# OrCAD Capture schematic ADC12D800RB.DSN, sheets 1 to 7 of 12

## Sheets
1 Title Page
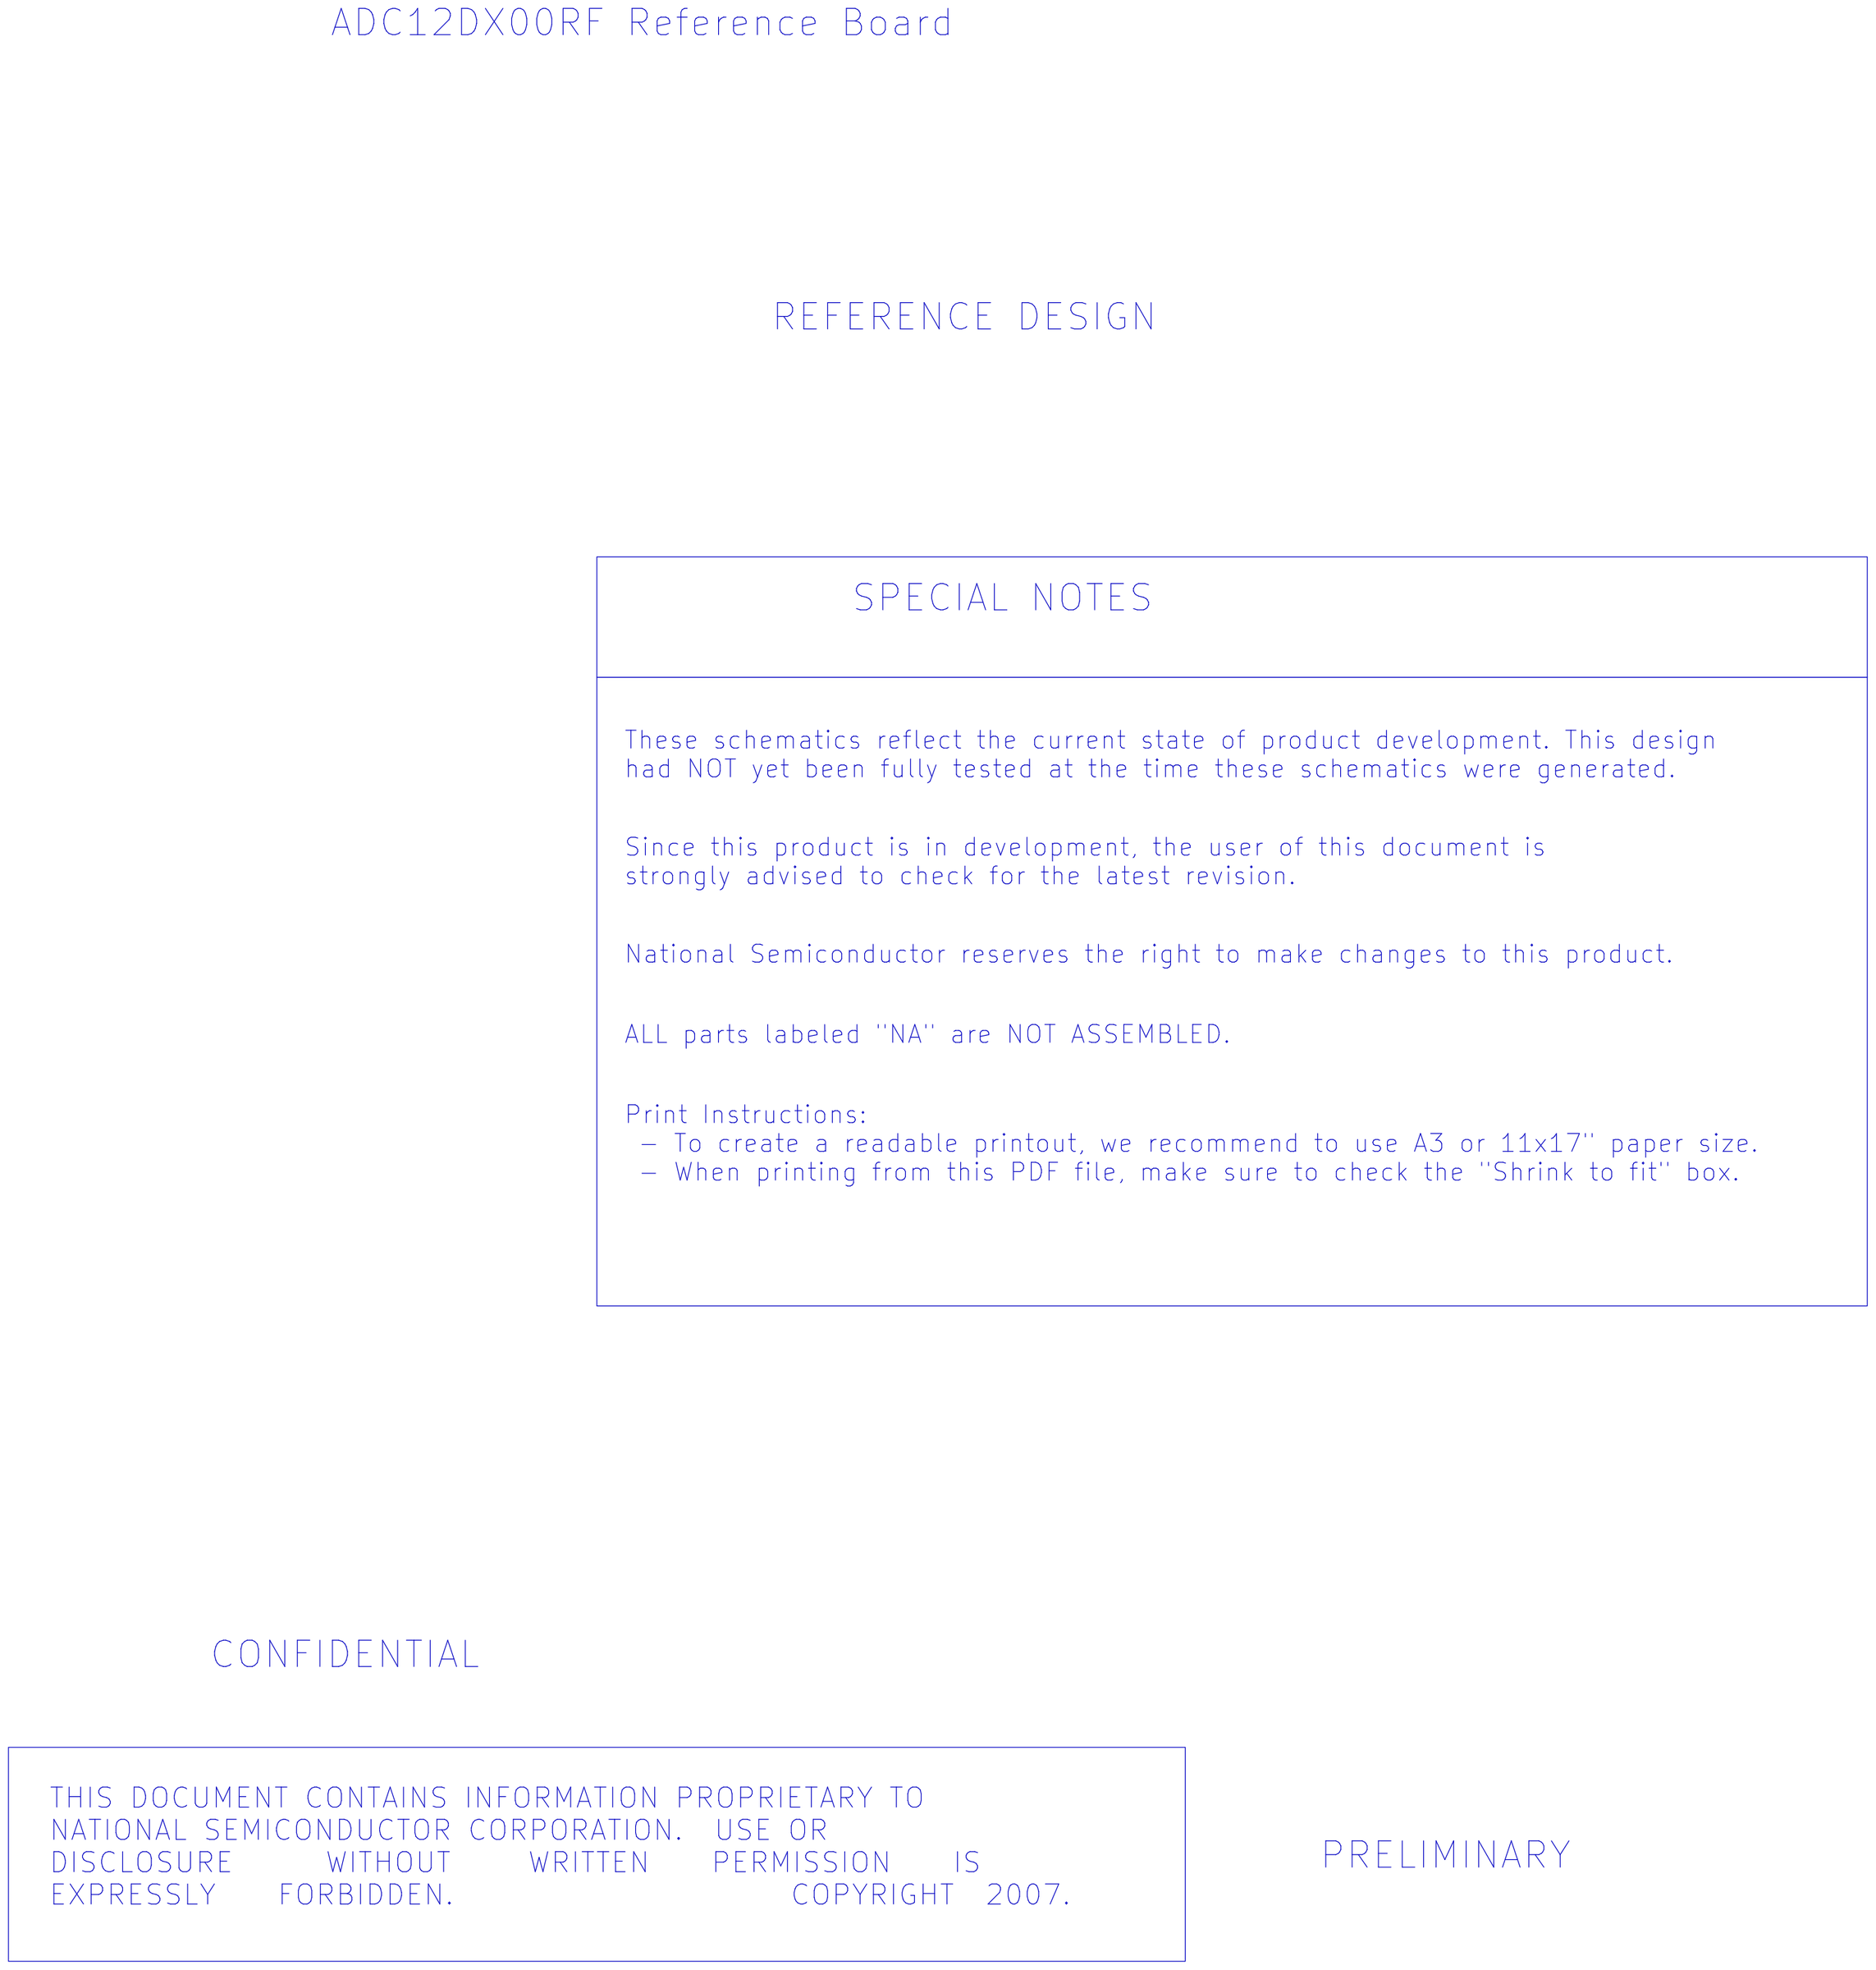
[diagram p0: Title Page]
2 TopBlock: size C
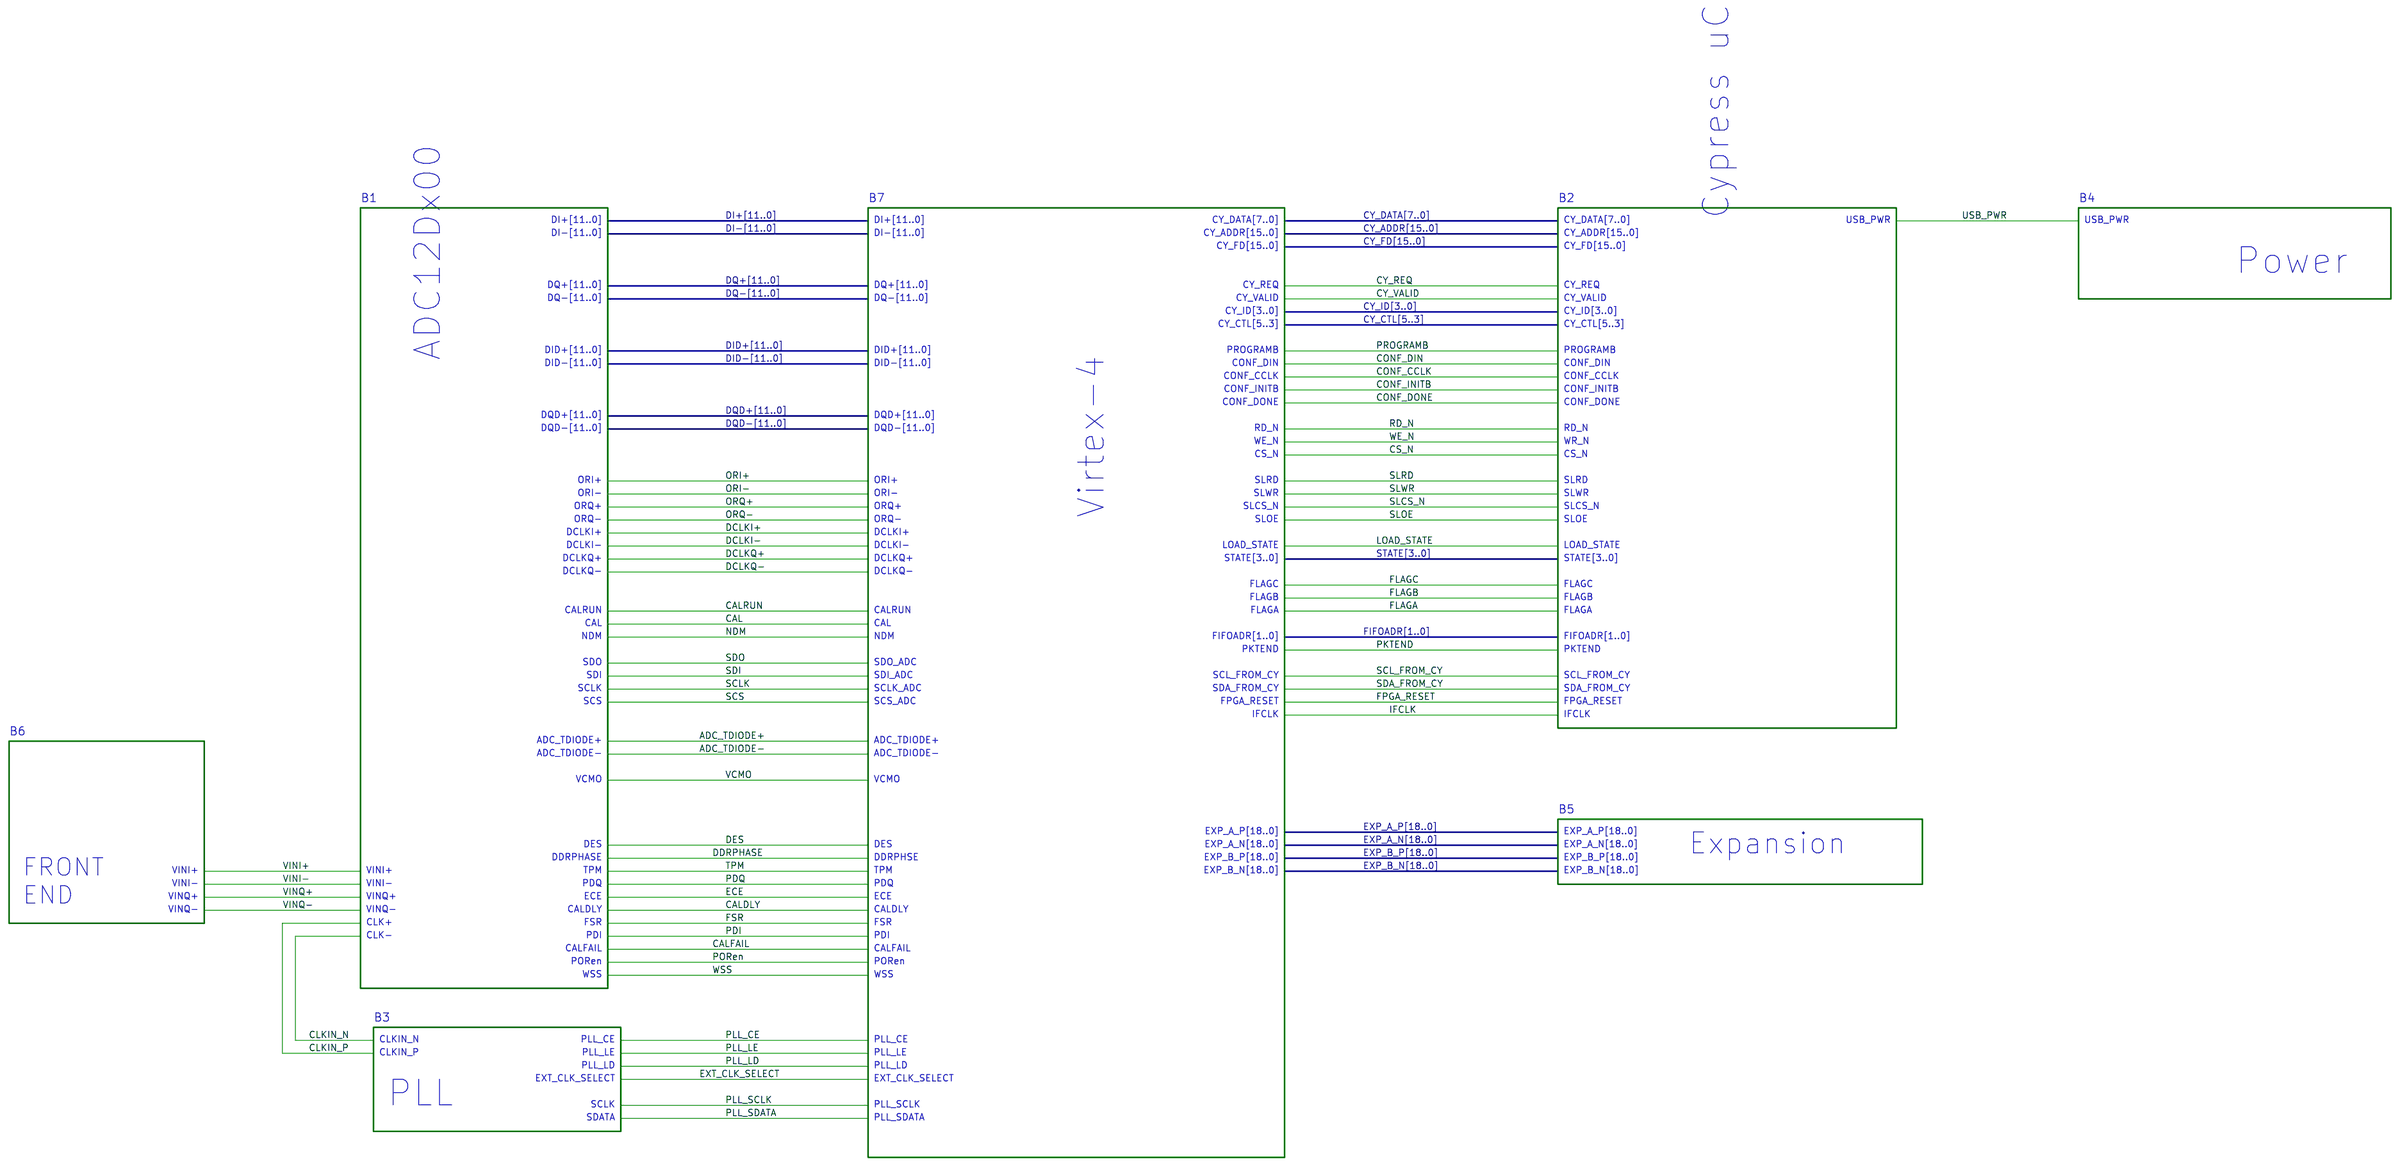
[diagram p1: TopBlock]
3 AD12DX00: size C; block B1
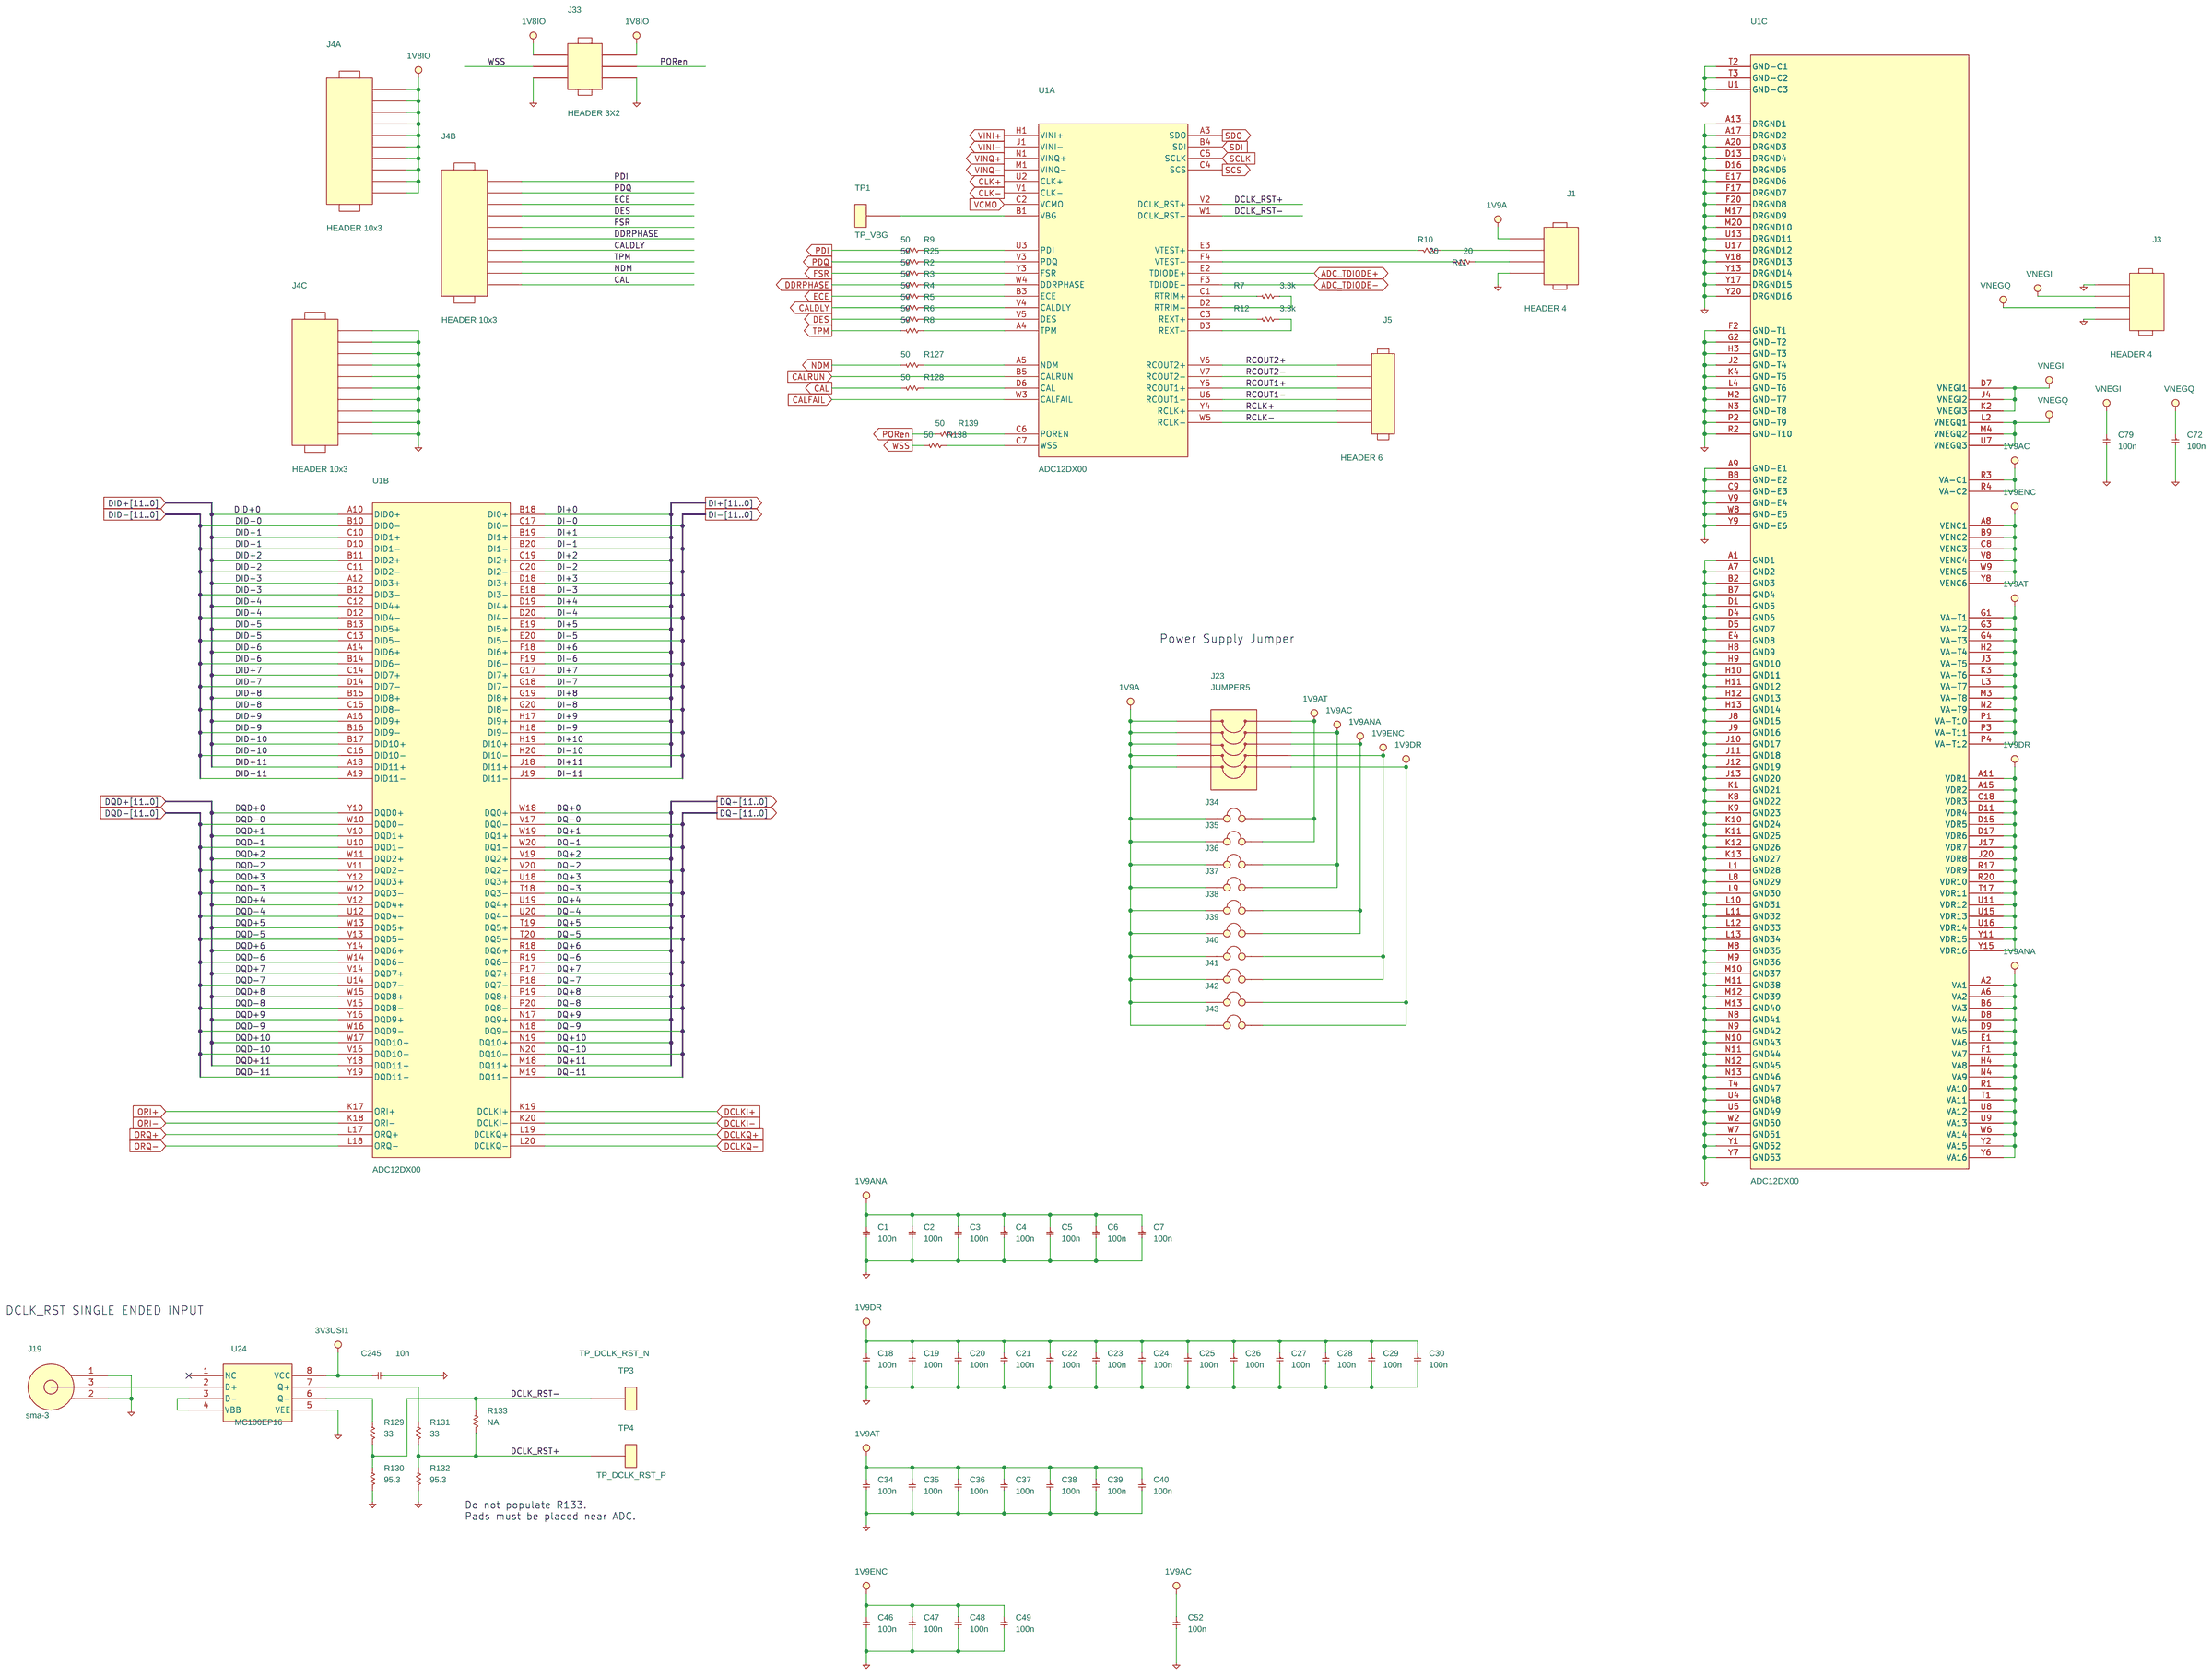
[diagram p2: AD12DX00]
4 Cypress: size C; block B2
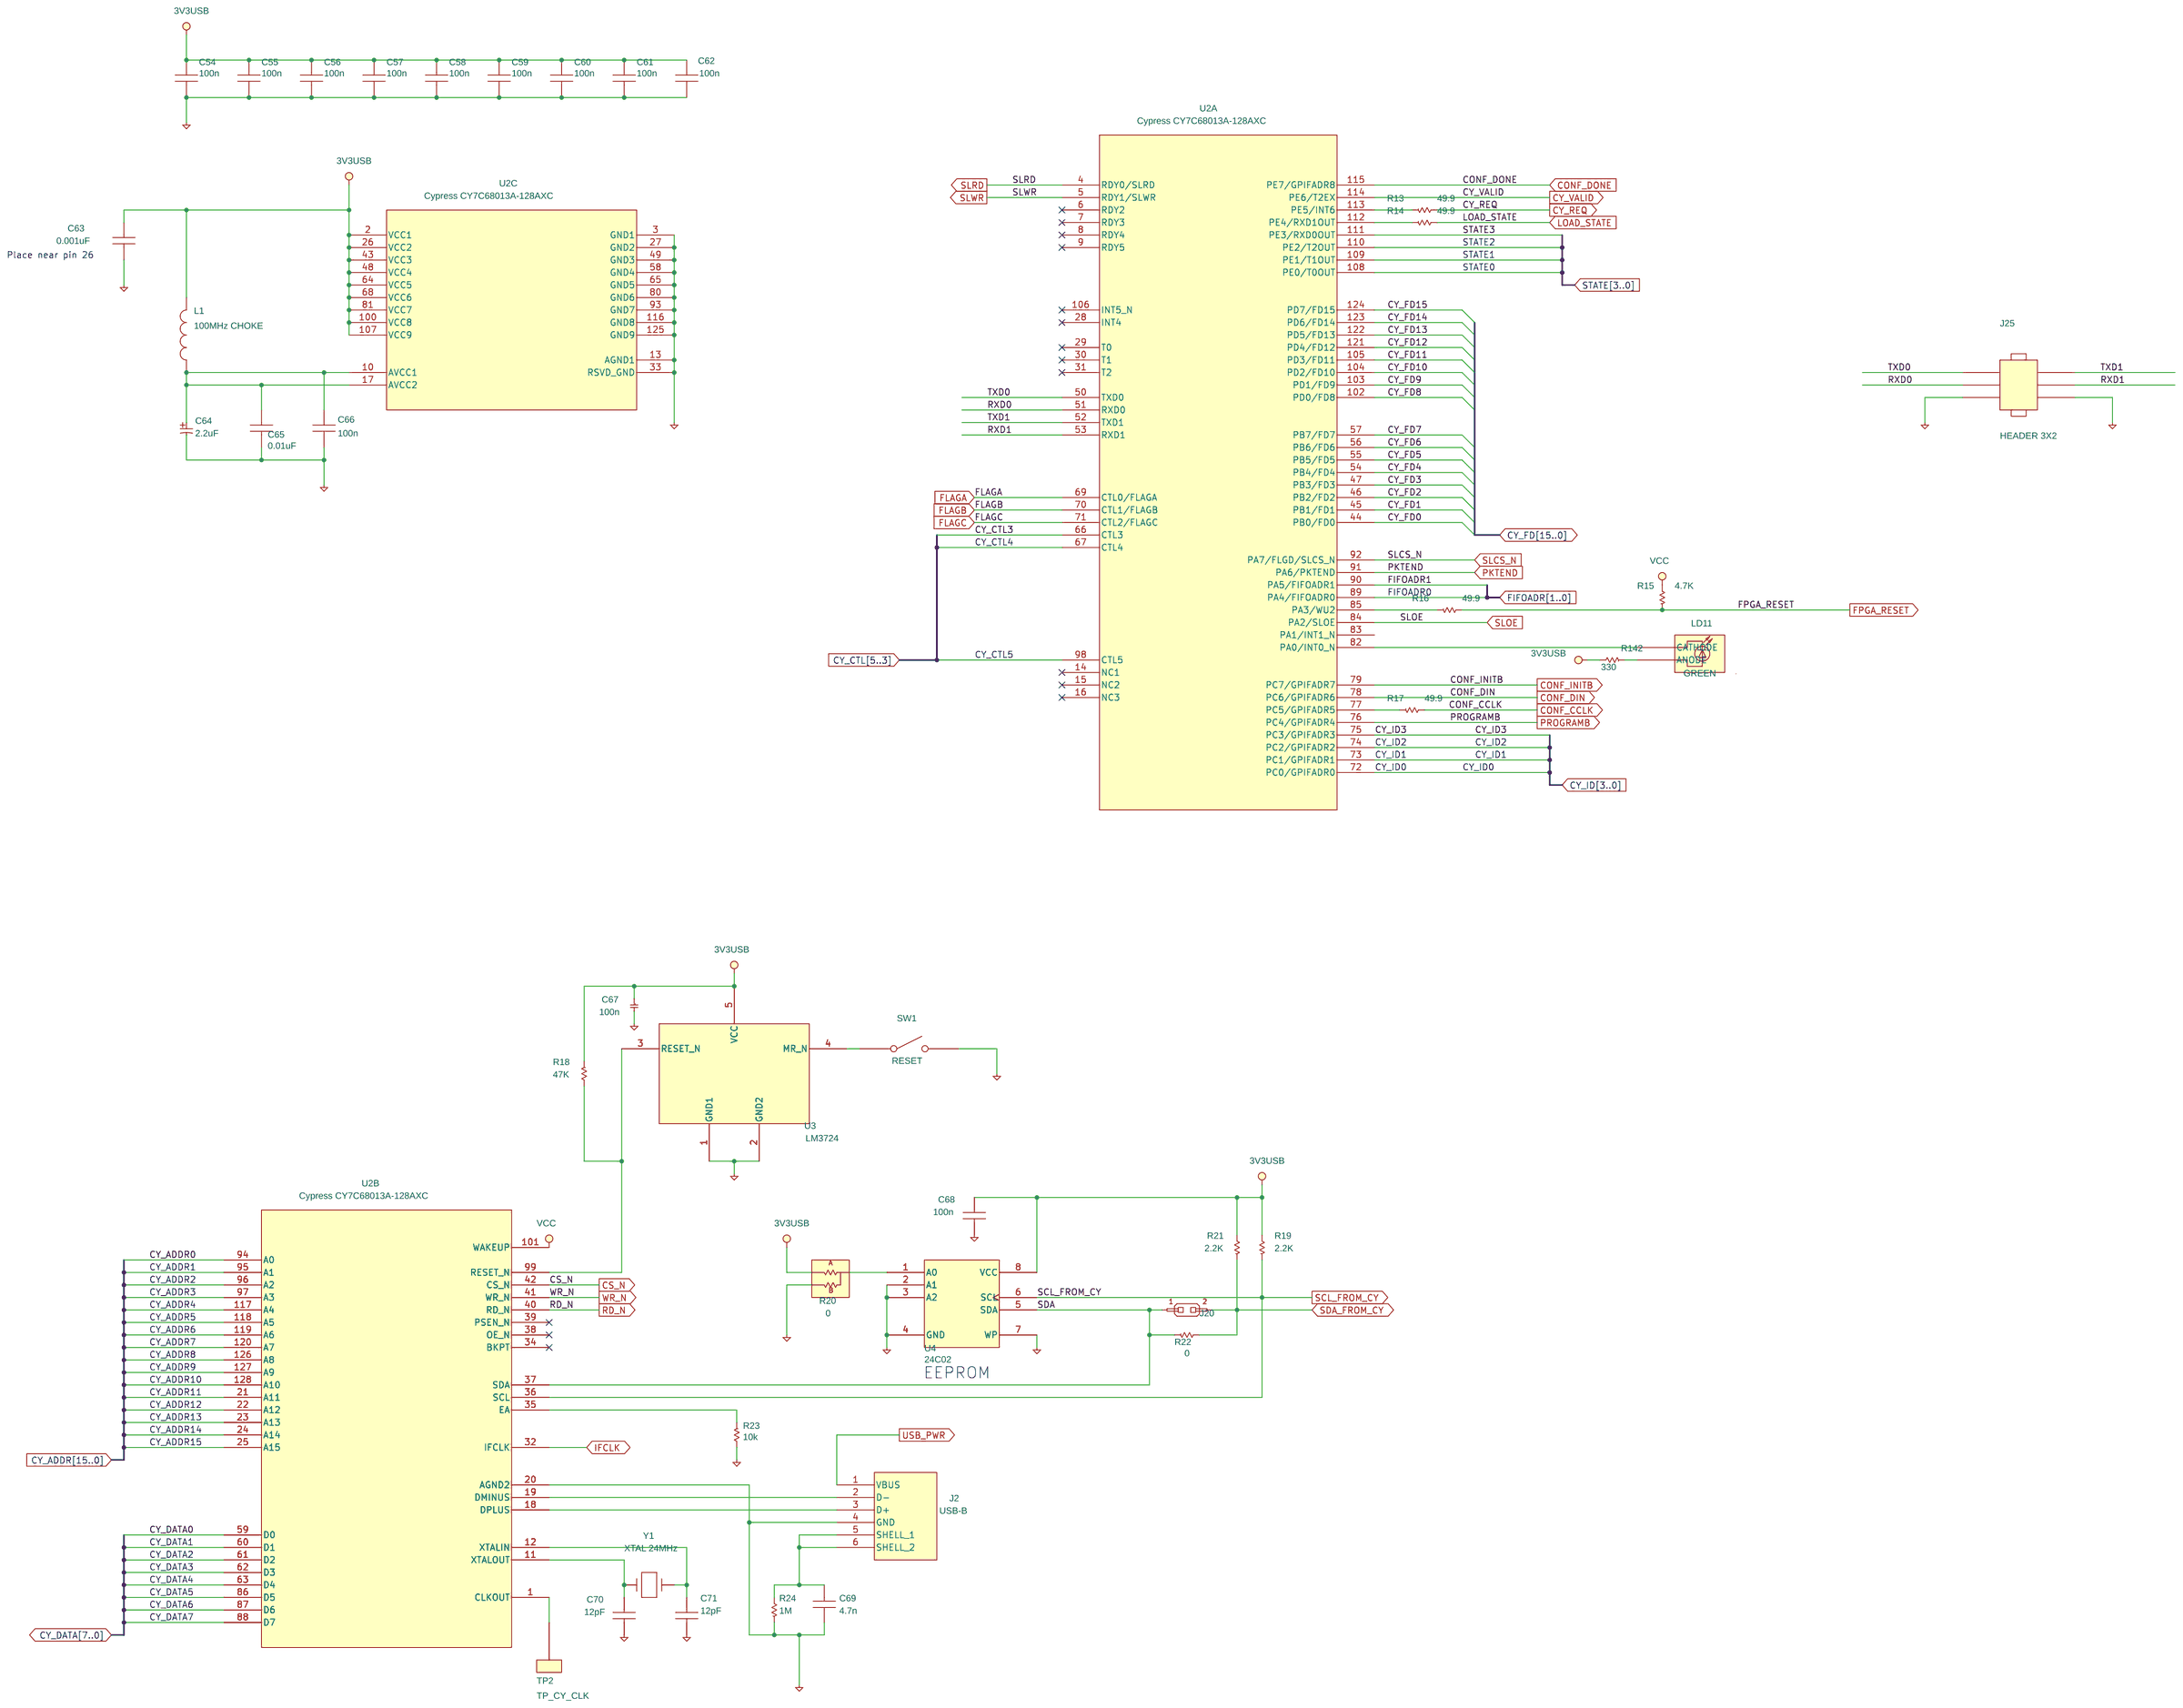
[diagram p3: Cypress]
5 Power1: size C; block B4
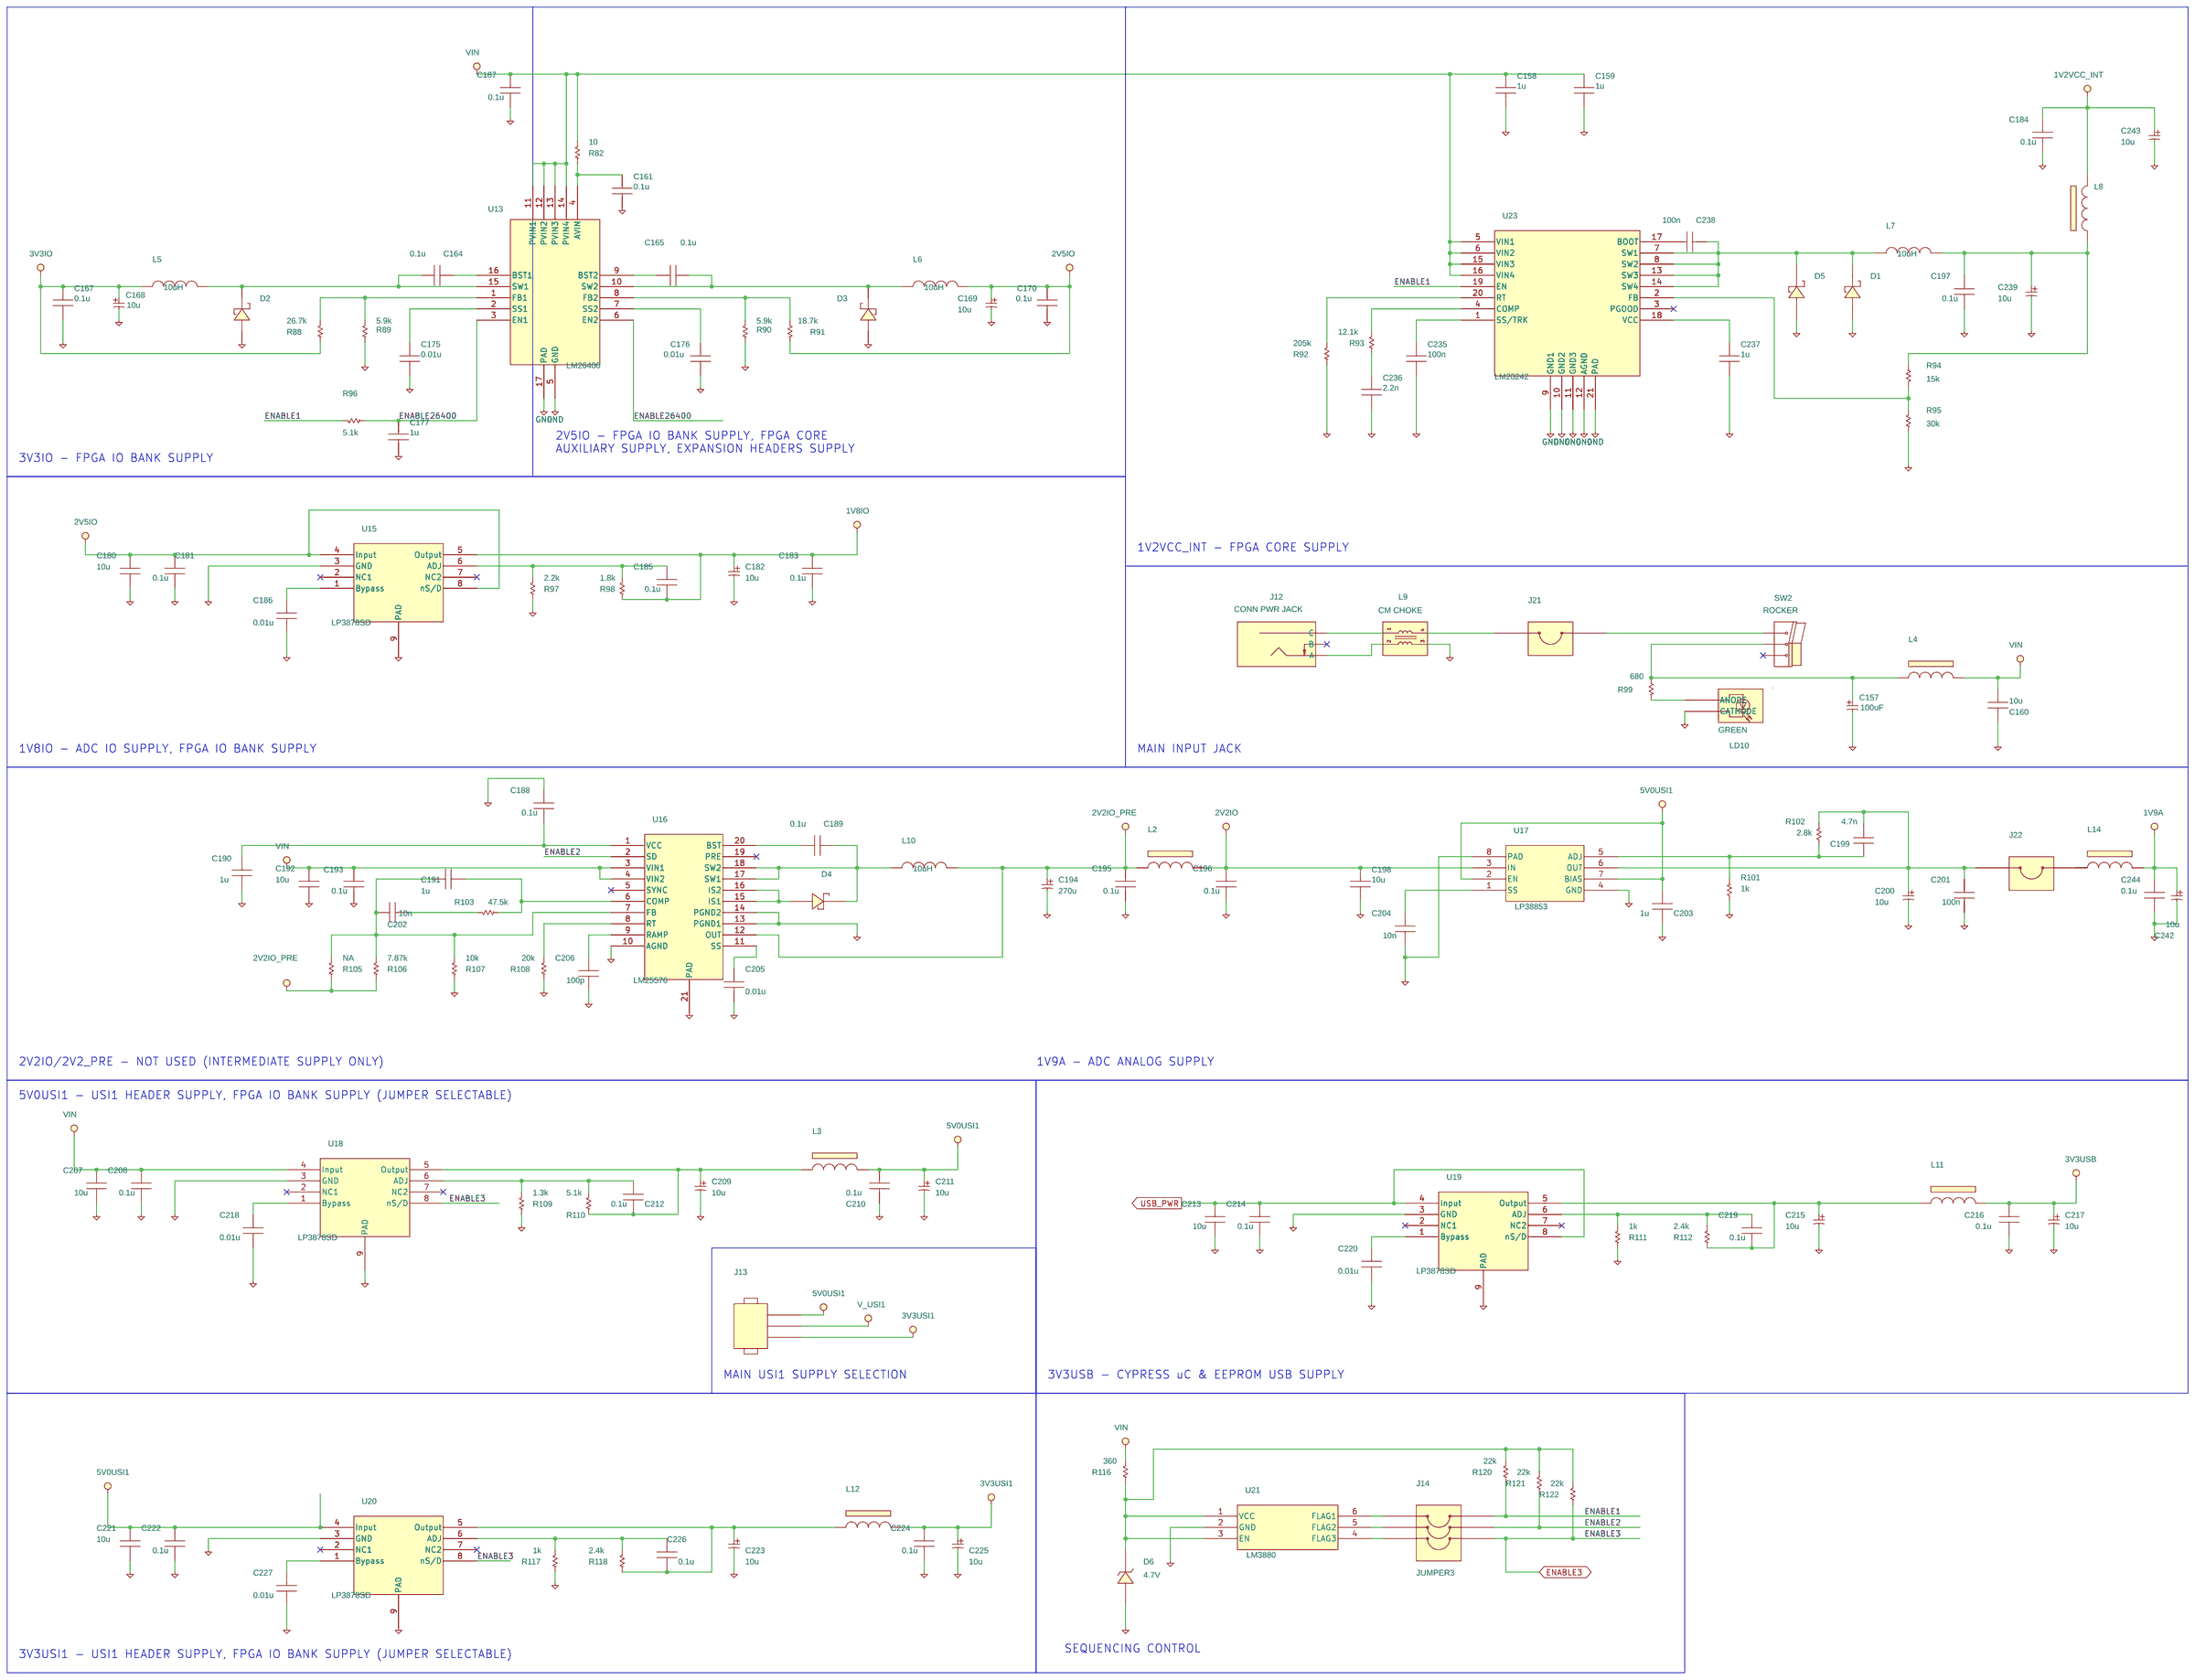
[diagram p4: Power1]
6 Power2: size C; block B4
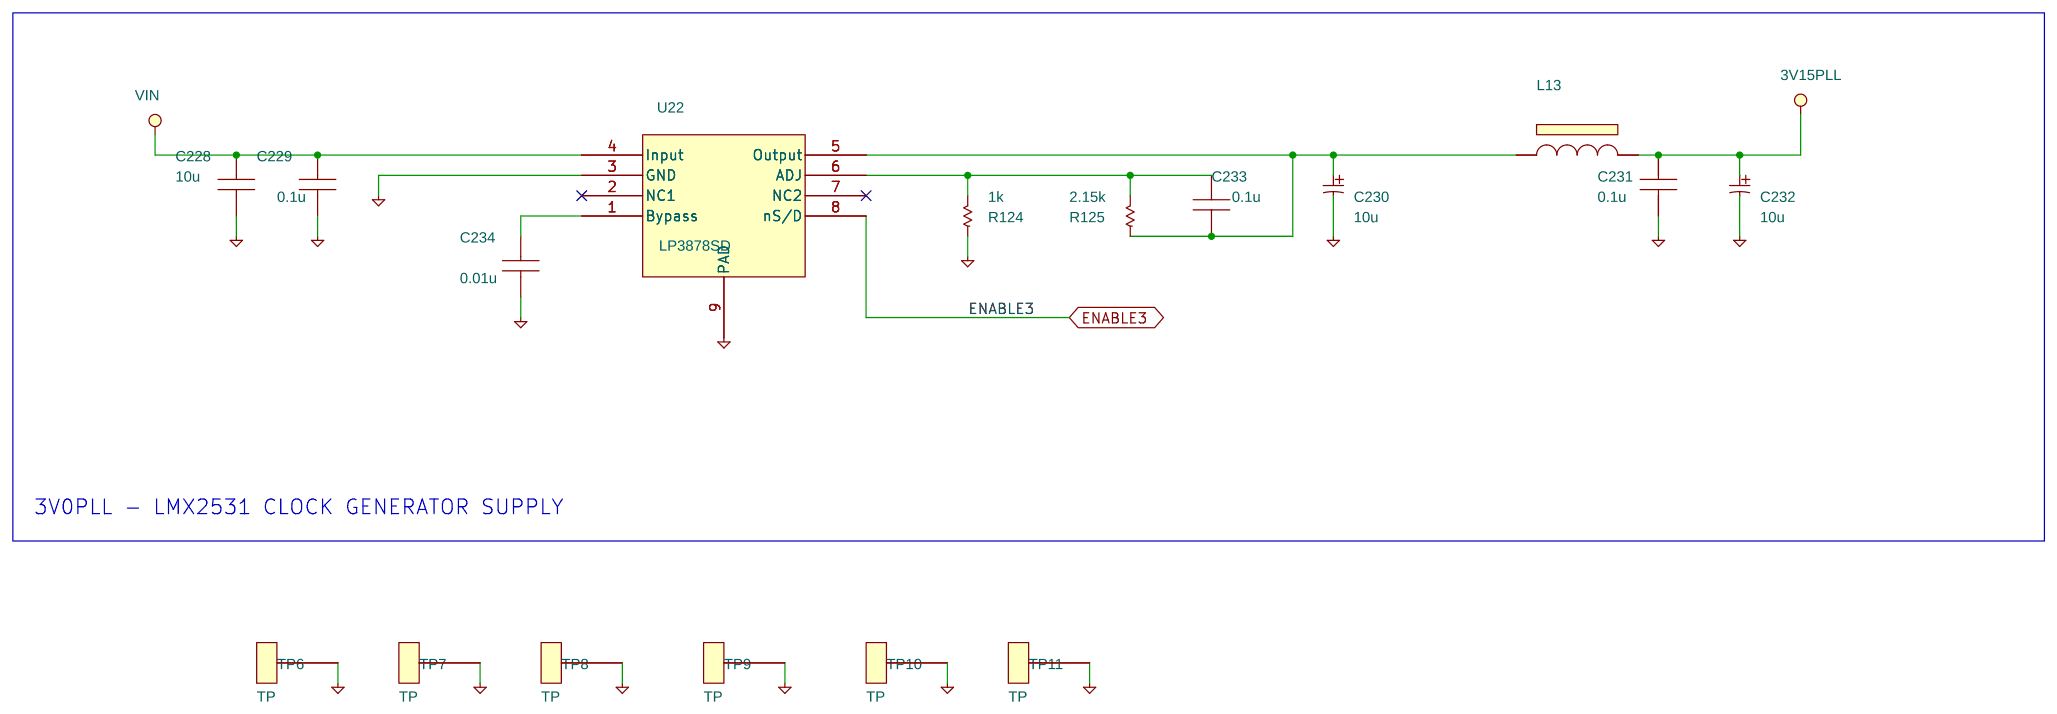
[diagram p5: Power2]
7 Expansion: size C; block B5
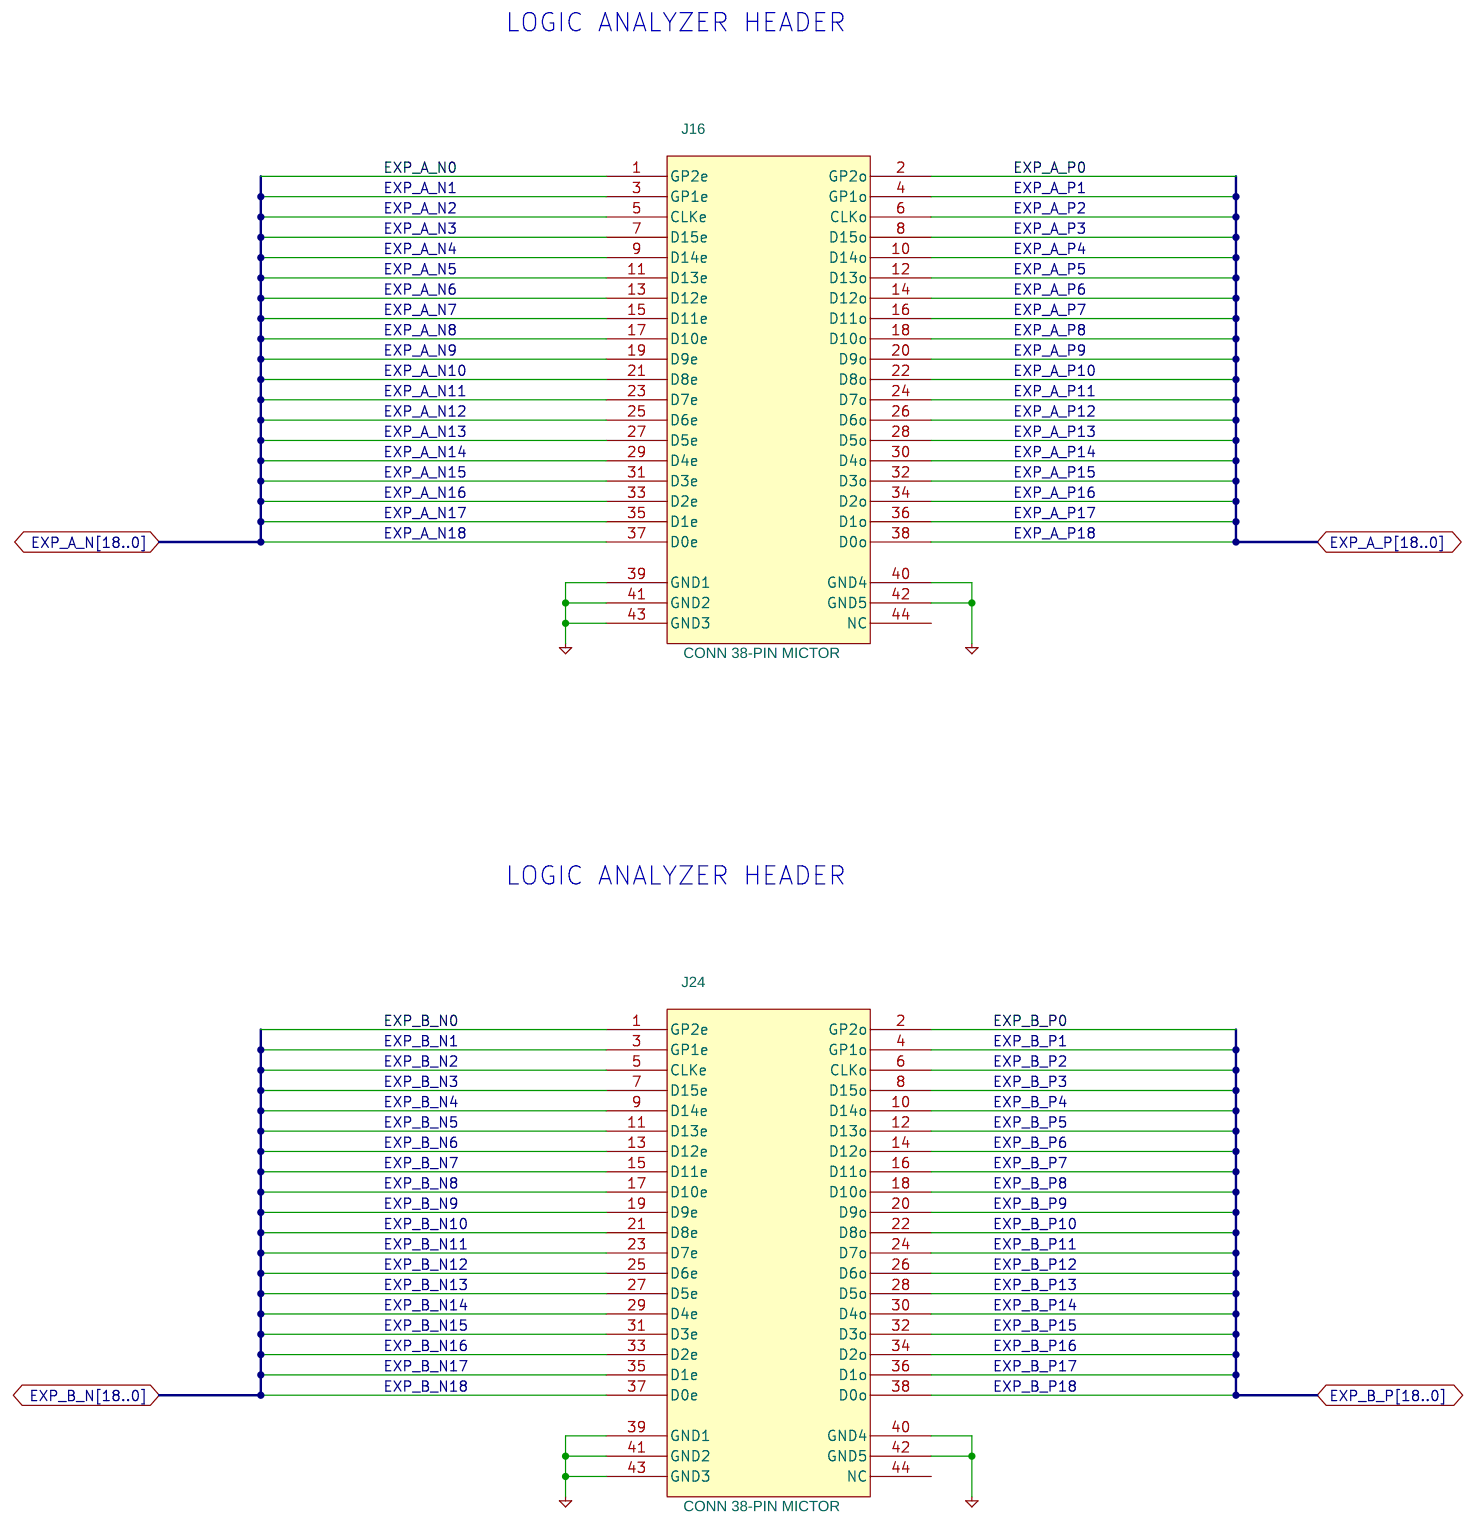
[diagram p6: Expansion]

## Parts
sheet AD12DX00
C1  100n  [c0402]
C2  100n  [c0402]
C3  100n  [c0402]
C4  100n  [c0402]
C5  100n  [c0402]
C6  100n  [c0402]
C7  100n  [c0402]
C18  100n  [c0402]
C19  100n  [c0402]
C20  100n  [c0402]
C21  100n  [c0402]
C22  100n  [c0402]
C23  100n  [c0402]
C24  100n  [c0402]
C25  100n  [c0402]
C26  100n  [c0402]
C27  100n  [c0402]
C28  100n  [c0402]
C29  100n  [c0402]
C30  100n  [c0402]
C34  100n  [c0402]
C35  100n  [c0402]
C36  100n  [c0402]
C37  100n  [c0402]
C38  100n  [c0402]
C39  100n  [c0402]
C40  100n  [c0402]
C46  100n  [c0402]
C47  100n  [c0402]
C48  100n  [c0402]
C49  100n  [c0402]
C52  100n  [c0402]
C72  100n  [c0402]
C79  100n  [c0402]
C245  10n  [c0402]
J1  HEADER 4  [blkcon_4x1]
J3  HEADER 4  [blkcon_4x1]
J4  HEADER 10x3  [blkcon_10x3]  (sections A,B,C)
J5  HEADER 6  [blkcon_6x1]
J19  sma-3  [RF_SMA_END_LAUNCH]
J23  JUMPER5  [blkcon_5x2]
J33  HEADER 3X2  [blkcon_3x2]
J34  jumper/sm/small  [sm_jumper]
J35  jumper/sm/small  [sm_jumper]
J36  jumper/sm/small  [sm_jumper]
J37  jumper/sm/small  [sm_jumper]
J38  jumper/sm/small  [sm_jumper]
J39  jumper/sm/small  [sm_jumper]
J40  jumper/sm/small  [sm_jumper]
J41  jumper/sm/small  [sm_jumper]
J42  jumper/sm/small  [sm_jumper]
J43  jumper/sm/small  [sm_jumper]
R2  50  [r0603]
R3  50  [r0603]
R4  50  [r0603]
R5  50  [r0603]
R6  50  [r0603]
R7  3.3k  [r0603]
R8  50  [r0603]
R9  50  [r0603]
R10  20  [r0603]
R11  20  [r0603]
R12  3.3k  [r0603]
R25  50  [r0603]
R127  50  [r0603]
R128  50  [r0603]
R129  33  [r0603]
R130  95.3  [r0603]
R131  33  [r0603]
R132  95.3  [r0603]
R133  NA  [r0603]
R138  50  [r0603]
R139  50  [r0603]
TP1  TP_VBG  [tp_smd_s35x28]
TP3  TP_DCLK_RST_N  [tp_smd_s35x28]
TP4  TP_DCLK_RST_P  [tp_smd_s35x28]
U1  ADC12DX00  [LLP60]  (sections A,B,C)
U24  MC100EP16  [TSSOP8_65M_WG4P9_L3]
sheet Cypress
C54  100n  [c0402]
C55  100n  [c0402]
C56  100n  [c0402]
C57  100n  [c0402]
C58  100n  [c0402]
C59  100n  [c0402]
C60  100n  [c0402]
C61  100n  [c0402]
C62  100n  [c0402]
C63  0.001uF  [c0603]
C64  2.2uF  [c3216]
C65  0.01uF  [c0402]
C66  100n  [c0402]
C67  100n  [c0603]
C68  100n  [c0402]
C69  4.7n  [c1206]
C70  12pF  [c1206]
C71  12pF  [c1206]
J2  USB-B  [usb-jack-b]
J20  JUMPER 2X1  [th_2_hdr1x2_m_str_100]
J25  HEADER 3X2  [blkcon_3x2]
L1  100MHz CHOKE  [r1206]
LD11  GREEN  [r1206]
R13  49.9  [r0603]
R14  49.9  [r0603]
R15  4.7K  [r0603]
R16  49.9  [r0603]
R17  49.9  [r0603]
R18  47K  [r1206]
R19  2.2K  [r1206]
R20  0  [0603_TRIPAD]
R21  2.2K  [r1206]
R22  0  [r0603]
R23  10k  [r0603]
R24  1M  [r1206]
R142  330  [r0603]
SW1  RESET  [sw_2p_6x3p5]
TP2  TP_CY_CLK  [tp_smd_s35x28]
U2  Cypress CY7C68013A-128AXC  [128tqfp]  (sections A,B,C)
U3  LM3724  [SOT23-stx]
U4  24C02  [soic8]
Y1  XTAL 24MHz  [hc49us]
sheet Expansion
J16  CONN 38-PIN MICTOR  [mictor_38_vf]
J24  CONN 38-PIN MICTOR  [mictor_38_vf]
sheet Power1
C157  100uF  [c6p6mmx6p6mm]
C158  1u  [c0805]
C159  1u  [c0805]
C160  10u  [c0805]
C161  0.1u  [c0402]
C164  0.1u  [c0402]
C165  0.1u  [c0402]
C167  0.1u  [c0402]
C168  10u  [c0805]
C169  10u  [c0805]
C170  0.1u  [c0402]
C175  0.01u  [c0402]
C176  0.01u  [c0402]
C177  1u  [c0402]
C180  10u  [c0805]
C181  0.1u  [c0402]
C182  10u  [c0805]
C183  0.1u  [c0402]
C184  0.1u  [c0402]
C185  0.1u  [c0402]
C186  0.01u  [c0402]
C187  0.1u  [c0402]
C188  0.1u  [c0402]
C189  0.1u  [c0402]
C190  1u  [c0402]
C191  1u  [c0402]
C192  10u  [c0805]
C193  0.1u  [c0402]
C194  270u  [c10p3mmx10p3mm]
C195  0.1u  [c0402]
C196  0.1u  [c0402]
C197  0.1u  [c0402]
C198  10u  [c0805]
C199  4.7n  [c0402]
C200  10u  [c0805]
C201  100n  [c0402]
C202  10n  [c0402]
C203  1u  [c0402]
C204  10n  [c0402]
C205  0.01u  [c0402]
C206  100p  [c0402]
C207  10u  [c0805]
C208  0.1u  [c0402]
C209  10u  [c0805]
C210  0.1u  [c0402]
C211  10u  [c0805]
C212  0.1u  [c0402]
C213  10u  [c0805]
C214  0.1u  [c0402]
C215  10u  [c0805]
C216  0.1u  [c0402]
C217  10u  [c0805]
C218  0.01u  [c0402]
C219  0.1u  [c0402]
C220  0.01u  [c0402]
C221  10u  [c0805]
C222  0.1u  [c0402]
C223  10u  [c0805]
C224  0.1u  [c0402]
C225  10u  [c0805]
C226  0.1u  [c0402]
C227  0.01u  [c0402]
C235  100n  [c0402]
C236  2.2n  [c0402]
C237  1u  [c0805]
C238  100n  [c0402]
C239  10u  [c0805]
C242  10u  [c0805]
C243  10u  [c0805]
C244  0.1u  [c0402]
D1  DIODE SCHOTTKY  [SOD_123_21]
D2  DIODE SCHOTTKY  [DO214_AB]
D3  DIODE SCHOTTKY  [DO214_AB]
D4  DIODE SCHOTTKY  [DO214_AB]
D5  DIODE SCHOTTKY  [SOD_123_21]
D6  4.7V  [SC_76]
J12  CONN PWR JACK  [JACK_POWER]
J13  HEADER 3  [blkcon_3x1]
J14  JUMPER3  [blkcon_3x2]
J21  JUMPER1  [blkcon_2x1]
J22  JUMPER1  [blkcon_2x1]
L2  INDUCTOR FERRITE/SM  [r0603]
L3  INDUCTOR FERRITE/SM  [r0603]
L4  INDUCTOR FERRITE/SM  [r0603]
L5  10uH  [EIA_481]
L6  10uH  [EIA_481]
L7  10uH  [EIA_481]
L8  INDUCTOR FERRITE/SM  [r0603]
L9  CM CHOKE  [choke_cm2545-b]
L10  10uH  [EIA_481]
L11  INDUCTOR FERRITE/SM  [r0603]
L12  INDUCTOR FERRITE/SM  [r0603]
L14  INDUCTOR FERRITE/SM  [r0603]
LD10  GREEN  [r1206]
R82  10  [r0603]
R88  26.7k  [r0603]
R89  5.9k  [r0603]
R90  5.9k  [r0603]
R91  18.7k  [r0603]
R92  205k  [r0603]
R93  12.1k  [r0603]
R94  15k  [r0603]
R95  30k  [r0603]
R96  5.1k  [r0603]
R97  2.2k  [r0603]
R98  1.8k  [r0603]
R99  680  [r0603]
R101  1k  [r0603]
R102  2.8k  [r0603]
R103  47.5k  [r0603]
R105  NA  [r0603]
R106  7.87k  [r0603]
R107  10k  [r0603]
R108  20k  [r0603]
R109  1.3k  [r0603]
R110  5.1k  [r0603]
R111  1k  [r0603]
R112  2.4k  [r0603]
R116  360  [r0603]
R117  1k  [r0603]
R118  2.4k  [r0603]
R120  22k  [r0603]
R121  22k  [r0603]
R122  22k  [r0603]
SW2  ROCKER  [SW_TH_RA_7101]
U13  LM26400  [TSSOP16_65M_WG6P4_L5]
U15  LP3878SD  [SOIC8_050_WG244_L200_EP]
U16  LM25576  [TSSOP20_65M_WG6P4_L6P5_EP]
U17  LP38853  [TO263_7p]
U18  LP3878SD  [SOIC8_050_WG244_L200_EP]
U19  LP3878SD  [SOIC8_050_WG244_L200_EP]
U20  LP3878SD  [SOIC8_050_WG244_L200_EP]
U21  LM3880  [SOT_23_6]
U23  LM20242  [TSSOP20_65M_WG6P4_L6P5_EP]
sheet Power2
C228  10u  [c0805]
C229  0.1u  [c0402]
C230  10u  [c0805]
C231  0.1u  [c0402]
C232  10u  [c0805]
C233  0.1u  [c0402]
C234  0.01u  [c0402]
L13  INDUCTOR FERRITE/SM  [r0603]
R124  1k  [r0603]
R125  2.15k  [r0603]
TP6  TP  [tp40]
TP7  TP  [tp40]
TP8  TP  [tp40]
TP9  TP  [tp40]
TP10  TP  [tp40]
TP11  TP  [tp40]
U22  LP3878SD  [SOIC8_050_WG244_L200_EP]

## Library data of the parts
C1-C7 C18-C30 C34-C40 C46-C49 C52 C72 C79 C245 = C-NON-POL: Capacitor, SMT 0402, MLC, X5R, 10%, 10V; Distributor: Digikey; Distributor Part Number: PCC2146TR-ND; Manufacturer: Panasonic; Manufacturer Part Number: ECJ-0EB1A104K
J1 J3 = HEADER_4
J4 = HEADER_10x3
J5 = HEADER_6
J19 = sma-3_0
J23 = JUMPER5
J25 J33 = HEADER_3X2
J34-J43 = jumper_sm_small
R2-R6 R8-R11 R23 R25 R92 R93 R101-R103 R105-R108 R124 R125 R127-R133 R138 R139 = RESISTOR_v2: RES 10K OHM 1/10W 5% 0603 SMD; Distributor: Digikey; Distributor Part Number: P10KGTR-ND; Manufacturer: Panasonic; Manufacturer Part Number: ERJ-3GEYJ103V
R7 R12 = RESISTOR_v2: RES 3300 OHM 1/10W 0.1% 0603 SMD; Distributor: Digikey; Manufacturer: Panasonic; Manufacturer Part Number: ERJ-3GEYJ470V
TP1-TP4 = TEST_POINT: TESTPOINT SMT; Distributor: N/A; Distributor Part Number: N/A; Manufacturer: N/A; Manufacturer Part Number: N/A
U1 = ADC12DX00
U24 = MC10EP16: Distributor: Newark; Distributor Part Number: 45J0940; Manufacturer: On Semiconductor; Manufacturer Part Number: MC100EP16DTR2G
C54-C62 C66 C68 C161 C164 C165 C167 C170 C175-C177 C181 C183-C191 C193 C195-C197 C199 C201-C206 C208 C210 C212 C214 C216 C218-C220 C222 C224 C226 C227 C229 C231 C233-C236 C238 C244 = CAPACITOR_NON-POL: Capacitor, SMT 0402, MLC, X5R, 10%, 10V; Distributor: Digikey; Distributor Part Number: PCC2146TR-ND; Manufacturer: Panasonic; Manufacturer Part Number: ECJ-0EB1A104K
C63 = CAPACITOR_NON-POL: CAP CERAMIC 0.001uF 0603 SMD; Distributor: Digikey; Distributor Part Number: 490-1451-1-ND; Manufacturer: Murata; Manufacturer Part Number: GRM1885C1H102JA01D
C64 = C-POLARISED: CAP 2.2UF SMD Size 3216; Distributor: Digikey; Distributor Part Number: 399-3690-1-ND; Manufacturer: Kemet; Manufacturer Part Number: T491A225K010AT
C65 = CAPACITOR_NON-POL: CAP CERAMIC 0.01uF 0402 SMD; Distributor: Digikey; Distributor Part Number: 399-1279-1-ND; Manufacturer: Kemet; Manufacturer Part Number: C0402C103J3RACTU
C67 = C-NON-POL: Capacitor, SMT 0603, MLC, X7R, 10%, 16V; Distributor: Digikey; Distributor Part Number: PCC1762TR-ND; Manufacturer: Panasonic; Manufacturer Part Number: ECJ-1VB1C104K
C69 = CAPACITOR_NON-POL: CAP CERAMIC 4.7nF 1206 SMD; Distributor: Digikey; Distributor Part Number: 399-1230-1-ND; Manufacturer: Kemet; Manufacturer Part Number: C1206C472K5RACTU
C70 C71 = CAPACITOR_NON-POL: CAP CERAMIC 12PF 50V NP0 1206; Distributor: Digikey; Distributor Part Number: 399-1193-1-ND; Manufacturer: Kemet; Manufacturer Part Number: C1206C120J5GACTU
J2 = USB-B_0: USB Connector Type B, Single Through Hole; COMPFIXED: NO; COMPGROUP: 0; COMPHEIGHT: 0.000; COMPKEY: NO; COMPLOC: [1080.000,430.000]; COMPLOCKED: NO; COMPROT: 0; COMPSIDE: TOP; DECOUPLER: NO; Distributor: Digikey; Distributor Part Number: ED90064-ND; FPLIST: TM/USB_TYPEB; MEMORY: NO; Manufacturer: Mill-Max; Manufacturer Part Number: 897-43-004-90-000000
J20 = JUMPER_2X1: HEADER 2X1 0.1" SP MALE STR; Distributor: Digikey; Distributor Part Number: S1012-36-ND; Manufacturer: Sullins; Manufacturer Part Number: PTC36SAAN
L1 = CHOKE: FERRITE CHIP 120 OHM 3000MA 1206; Distributor: Digikey; Distributor Part Number: 490-1056-1-ND; Manufacturer: Murata; Manufacturer Part Number: BLM31PG121SN1L
LD11 = LED_SNGLE_PANEL: LED 2X3MM 565NM GRN WTR CLR SMD; Distributor: Digikey; Distributor Part Number: 67-1357-1-ND; Manufacturer: Lumex; Manufacturer Part Number: SML-LX1206GC-TR
R13 R14 R16 R17 = RESISTOR_v2: RES 47 OHM 1/10W 5% 0603 SMD; Distributor: Digikey; Distributor Part Number: P47GTR-ND; Manufacturer: Panasonic; Manufacturer Part Number: ERJ-3GEYJ470V
R15 R142 = RESISTOR_v2: RES 4.7K OHM 1/10W 5% 0603 SMD; Distributor: Digikey; Distributor Part Number: P4.7KGTR-ND; Manufacturer: Panasonic; Manufacturer Part Number: ERJ-3GEYJ472V
R18 = RESISTOR_v2: RES47K OHM 1/4W 1% 1206 SMD; Distributor: Digikey; Distributor Part Number: P47.0KFCT-ND; Manufacturer: Panasonic; Manufacturer Part Number: ERJ-8ENF4702V
R19 R21 = RESISTOR_v2: RES 2.2K OHM 1/10W 5% 1206 SMD; Distributor: Digikey; Distributor Part Number: P2.2KETR-ND; Manufacturer: Panasonic; Manufacturer Part Number: ERJ-8GEYJ222V
R20 = RESISTOR_TRIPAD: RES 0 OHM 1/10W 5% 0603 SMD; Distributor: Digikey; Distributor Part Number: P0.0GTR-ND; Manufacturer: Panasonic; Manufacturer Part Number: ERJ-3GEY0R00V
R22 = RESISTOR_v2: RES 0 OHM 1/10W 5% 0603 SMD; Distributor: Digikey; Distributor Part Number: P0.0GTR-ND; Manufacturer: Panasonic; Manufacturer Part Number: ERJ-3GEY0R00V
R24 = RESISTOR_v2: RES 1M OHM 1/10W 5% 1206 SMD; Distributor: Digikey; Distributor Part Number: P1.0METR-ND; Manufacturer: Panasonic; Manufacturer Part Number: ERJ-8GEYJ105V
SW1 = SW_KEY-SPST: SWITCH TACT MOM 130GF H=5MM; Distributor: Digikey; Distributor Part Number: CKN9017-ND; Manufacturer: ITT Industries/C&K Div; Manufacturer Part Number: PTS635SL50
U2 = Cypress_CY7C64613-80NC: USB MICROCONTROLLER FX2LP 128 PIN; Distributor: Cypress; Distributor Part Number: CY7C68013A-128AXC; Manufacturer: Cypress; Manufacturer Part Number: CY7C68013A-128AXC
U3 = LM3722: 5-pin uP reset ckt, sot23-5 pkg, LM3724EM5-3.08; Distributor: National Semiconductor; Distributor Part Number: LM3724EM5-3.08; Manufacturer: National Semiconductor; Manufacturer Part Number: LM3724EM5-3.08
U4 = 24C02_SO8_0: IC SRL EEPROM 2K (256 x 8) 1.8V 8SOIC 2 WIRE; Distributor: Digikey; Distributor Part Number: AT24C02BN-10SU-1.8-ND; Manufacturer: Atmel; Manufacturer Part Number: AT24C02BN-10SU-1.8
Y1 = CRYSTAL: CRYSTAL 24.000MHZ; Distributor: Digikey; Distributor Part Number: XC1001CT-ND; Manufacturer: ECS Inc.; Manufacturer Part Number: ECS-240-12-5PX-TR
J16 J24 = CONN_38-PIN_MICTOR
C157 = C-POLARISED: CAP ALUM ELECTROLYTIC 100UF 10V; Distributor: Digikey; Distributor Part Number: 565-2429-2-ND; Manufacturer: United Chemi-Con; Manufacturer Part Number: EMVY100ADA101MF55G
C158 C159 C237 = CAPACITOR_NON-POL: CAP NONPOL TDK 1UF X5R; Manufacturer: TDK; Manufacturer Part Number: C2012X5J1061A
C160 C180 C192 C213 = CAPACITOR_NON-POL: CAP NONPOL TDK 1UF X5R; Manufacturer: TDK; Manufacturer Part Number: C2012X5R0J106M
C168 C169 C182 C200 C209 C211 C215 C217 C223 C225 C230 C232 C239 C242 C243 = C-POLARISED: CAP POL TDK 10UF X5R; Distributor: Digikey; Distributor Part Number: 445-1363-2-ND; Manufacturer: TDK; Manufacturer Part Number: C2012X5R0J1061M
C194 = C-POLARISED: CAP LOW ESR 6V; Distributor: Digikey; Distributor Part Number: 565-3069-2-ND; Manufacturer: United Chemi-Con; Manufacturer Part Number: APXA100ARA271MJ80G
C198 C207 C221 C228 = CAPACITOR_NON-POL: CAP NONPOL TDK 1UF X5R; Manufacturer: TDK; Manufacturer Part Number: C2012X5R0J1061A
D1 D5 = DIODE_SCHOTTKY: DIODE SCHOTTKY 0.5A 40V; Manufacturer: On Semiconductor; Manufacturer Part Number: MBR0540
D2-D4 = DIODE_SCHOTTKY: DIODE SCHOTTKY SMD 3W; Manufacturer: On Semiconductor; Manufacturer Part Number: MBRS320
D6 = DIODE_ZENER: Diode Zener 4.7V; Distributor: Digikey; Distributor Part Number: MAZ80470MLCT; Manufacturer: Panasonic; Manufacturer Part Number: MAZ80470ML
J12 = CONN_PWR_JACK: CONN PWR JACK 2.5X5.5MM HIGH CUR; Distributor: Digikey; Distributor Part Number: CP-102BH-ND; Manufacturer: CUI Inc; Manufacturer Part Number: PJ-102BH
J13 = HEADER_3
J14 = JUMPER3
J21 J22 = JUMPER1
L2 = INDUCTOR_FERRITE_SM: Murata Ferrite Bead SM 2.5A; Manufacturer: Murata; Manufacturer Part Number: BLM18SG221TN1
L3 L11-L13 = INDUCTOR_FERRITE_SM: Murata Ferrite Bead SM 1.5A; Manufacturer: Murata; Manufacturer Part Number: BLM18SG331TN1
L4 L8 L14 = INDUCTOR_FERRITE_SM: Murata Ferrite Bead SM 6A; Manufacturer: Murata; Manufacturer Part Number: BLM18SG260TN1
L5-L7 L10 = INDUCTOR: INDUCTOR COILCRAFT SMD 10UH; Manufacturer: Coilcraft; Manufacturer Part Number: MSS1246-103ML
L9 = INDUCTOR_CM_CHOKE: CHOKE COMMON MODE 170 OHMS PCB; Distributor: Digikey; Distributor Part Number: 240-2485-ND; Manufacturer: Steward; Manufacturer Part Number: CM2545X171B-01
LD10 = LED_SNGLE_PANEL: LED 3MM RA FAULT-IND GRN PC MNT; Distributor: Digikey; Distributor Part Number: 67-1236-ND; Manufacturer: Lumex; Manufacturer Part Number: SSF-LXH103GD
R82 = RESISTOR_v2: RES 10 OHM 1/10W 5% 0603 SMD; Distributor: Digikey; Distributor Part Number: P10GTR-ND; Manufacturer: Panasonic; Manufacturer Part Number: ERJ-3GEYJ103V
R88 = RESISTOR_v2: RES 26.7K OHM 1/10W 1% 0603 SMD; Distributor: Digikey; Distributor Part Number: P26.7KABTR-ND; Manufacturer: Panasonic; Manufacturer Part Number: ERJ-1GEF2672C
R89 R90 = RESISTOR_v2: RES 5.9K OHM 1/10W 1% 0603 SMD; Distributor: Digikey; Distributor Part Number: 311-5.9KDTR-ND; Manufacturer: Yageo; Manufacturer Part Number: RT0603DRD075K9L
R91 = RESISTOR_v2: RES 18.7K OHM 1/10W 1% 0603 SMD; Distributor: Digikey; Distributor Part Number: P18.7KHTR-ND; Manufacturer: Panasonic; Manufacturer Part Number: ERJ-3EKF1872V
R94 = RESISTOR_v2: RES 15K OHM 1/10W 5% 0603 SMD; Distributor: Digikey; Distributor Part Number: P15KGTR-ND; Manufacturer: Panasonic; Manufacturer Part Number: ERJ-3GEYJ153V
R95 = RESISTOR_v2: RES 30K OHM 1/10W 5% 0603 SMD; Distributor: Digikey; Distributor Part Number: P30KGTR-ND; Manufacturer: Panasonic
R96 = RESISTOR_v2: RES 5.1K OHM 1/10W 5% 0603 SMD; Distributor: Digikey; Distributor Part Number: P5.1KGTR-ND; Manufacturer: Panasonic
R97 = RESISTOR_v2: RES 2.2K OHM 1/10W 5% 0603 SMD; Distributor: Digikey; Distributor Part Number: P2.2KGTR-ND; Manufacturer: Panasonic
R98 = RESISTOR_v2: RES 1.8K OHM 1/10W 5% 0603 SMD; Distributor: Digikey; Distributor Part Number: P1.8KGTR-ND; Manufacturer: Panasonic
R99 = RESISTOR_v2: RES 680 OHM 1/10W 5% 0603 SMD; Distributor: Digikey; Distributor Part Number: P680GTR-ND; Manufacturer: Panasonic; Manufacturer Part Number: ERJ-3GEYJ681V
R109 = RESISTOR_v2: RES 1.3K OHM 1/10W 5% 0603 SMD; Distributor: Digikey; Distributor Part Number: P1.3KGTR-ND; Manufacturer: Panasonic
R110 = RESISTOR_v2: RES 10K OHM 1/10W 5% 0603 SMD; Distributor: Digikey; Distributor Part Number: P5.1KGTR-ND; Manufacturer: Panasonic
R111 R117 = RESISTOR_v2: RES 1K OHM 1/10W 5% 0603 SMD; Distributor: Digikey; Distributor Part Number: P1KGTR-ND; Manufacturer: Panasonic
R112 R118 = RESISTOR_v2: RES 2.4K OHM 1/10W 5% 0603 SMD; Distributor: Digikey; Distributor Part Number: P2.4KGTR-ND; Manufacturer: Panasonic
R116 = RESISTOR_v2: RES 360 OHM 1/10W 5% 0603 SMD; Distributor: Digikey; Distributor Part Number: P360GCT-ND; Manufacturer: Panasonic; Manufacturer Part Number: ERJ-3GEYJ361V
R120-R122 = RESISTOR_v2: RES 22K OHM 1/10W 5% 0402 SMD; Distributor: Digikey; Distributor Part Number: P22KGTR-ND; Manufacturer: Panasonic; Manufacturer Part Number: ERJ-3GEYJ103V
SW2 = SW-DPST-2P: SWITCH ROCKER SPDT HORZ ACT RA; Distributor: Digikey; Distributor Part Number: CKN2005-ND; Manufacturer: ITT Industries/C&K Div; Manufacturer Part Number: 7101J1AQE2; NC: 4,5
U13 = LM26400: IC REG DUAL BUCK 2A; Manufacturer: National Semiconductor
U15 U18-U20 U22 = LP3878SD: IC REG LOW NOISE 0.5A; Manufacturer: National Semiconductor
U16 = LM25576: IC REG SIMPLE SWITCHER 3A; Manufacturer: National Semiconductor
U17 = LP38853
U21 = LM3880
U23 = LM20242
TP6-TP11 = TEST_POINT: TESTPOINT; Distributor: N/A; Distributor Part Number: N/A; Manufacturer: N/A; Manufacturer Part Number: N/A

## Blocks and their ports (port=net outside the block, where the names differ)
B1 = schematic ADC12DX00, on sheet TopBlock: VINI+, VINI-, VINQ+, VINQ-, CLK+=CLKIN_P, CLK-=CLKIN_N, CAL, VCMO, CALRUN, SDI, SCLK, SDO, ORQ+, ORQ-, ORI+, ORI-, DCLKQ+, DCLKQ-, DCLKI+, DCLKI-, DID+[11..0], DQD+[11..0], DI+[11..0], DQ+[11..0], DID-[11..0], DI-[11..0], DQD-[11..0], DQ-[11..0], ADC_TDIODE+, ADC_TDIODE-, NDM, SCS, PDI, FSR, CALDLY, ECE, PDQ, TPM, DDRPHASE, DES, CALFAIL, WSS, PORen
B7 = schematic FPGA, on sheet TopBlock: SCL_FROM_CY, SDA_FROM_CY, ADC_TDIODE+, ADC_TDIODE-, CONF_INITB, PROGRAMB, CONF_CCLK, CONF_DONE, CONF_DIN, CY_CTL[5..3], LOAD_STATE, STATE[3..0], EXT_CLK_SELECT, ORQ+, DI-[11..0], ORQ-, DCLKI+, ORI+, DQ-[11..0], DCLKI-, DQD-[11..0], ORI-, DQD+[11..0], DCLKQ+, DI+[11..0], DQ+[11..0], DID-[11..0], DID+[11..0], DCLKQ-, SLCS_N, CY_VALID, CY_ID[3..0], CY_DATA[7..0], FIFOADR[1..0], FPGA_RESET, CY_FD[15..0], SLRD, FLAGA, CS_N, SLWR, FLAGB, WE_N, FLAGC, RD_N, SLOE, CY_REQ, CY_ADDR[15..0], PKTEND, PLL_LD, PLL_SCLK, PLL_LE, PLL_CE, CALRUN, SCS_ADC=SCS, CAL, PLL_SDATA, NDM, SCLK_ADC=SCLK, SDI_ADC=SDI, SDO_ADC=SDO, VCMO, PDI, FSR, CALDLY, ECE, DDRPHSE=DDRPHASE, PDQ, TPM, DES, IFCLK, EXP_A_P[18..0], EXP_A_N[18..0], EXP_B_P[18..0], EXP_B_N[18..0], CALFAIL, WSS, PORen
B6 = schematic Front End, on sheet TopBlock: VINI+, VINI-, VINQ+, VINQ-
B2 = schematic Cypress, on sheet TopBlock: CY_DATA[7..0], USB_PWR, CS_N, WR_N=WE_N, RD_N, FPGA_RESET, SLOE, PKTEND, SLCS_N, LOAD_STATE, CONF_DONE, CY_VALID, CY_REQ, FLAGA, FLAGB, FLAGC, SLRD, SLWR, CONF_INITB, PROGRAMB, CONF_CCLK, SCL_FROM_CY, CY_ADDR[15..0], CY_FD[15..0], CY_ID[3..0], CY_CTL[5..3], STATE[3..0], FIFOADR[1..0], SDA_FROM_CY, CONF_DIN, IFCLK
B4 = schematic Power, on sheet TopBlock: USB_PWR
B3 = schematic PLL, on sheet TopBlock: SDATA=PLL_SDATA, PLL_LE, PLL_CE, EXT_CLK_SELECT, PLL_LD, CLKIN_P, CLKIN_N, SCLK=PLL_SCLK
B5 = schematic Expansion, on sheet TopBlock: EXP_A_P[18..0], EXP_A_N[18..0], EXP_B_P[18..0], EXP_B_N[18..0]

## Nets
1V2VCC_INT: C184.1 C243.1(POS) L8.2 ; also on sheet 11
1V8IO: C182.1(POS) C183.1 C185.2 J4.1 J4.4 J4.7 J4.10 J4.13 J4.16 J4.19 J4.22 J4.25 J4.28 J33.1 J33.2 R98.1 U15.5(Output) ; also on sheet 10 11
1V9A: C242.1(POS) C244.1 J1.1 J23.1 J23.3 J23.5 J23.7 J23.9 J34.1 J35.1 J36.1 J37.1 J38.1 J39.1 J40.1 J41.1 J42.1 J43.1 L14.2
1V9AC: C52.1 J23.4 J36.2 J37.2 U1.R3(VA-C1) U1.R4(VA-C2)
1V9ANA: C1.1 C2.1 C3.1 C4.1 C5.1 C6.1 C7.1 J23.6 J38.2 J39.2 U1.A2(VA1) U1.A6(VA2) U1.B6(VA3) U1.D8(VA4) U1.D9(VA5) U1.E1(VA6) U1.F1(VA7) U1.H4(VA8) U1.N4(VA9) U1.R1(VA10) U1.T1(VA11) U1.U8(VA12) U1.U9(VA13) U1.W6(VA14) U1.Y2(VA15) U1.Y6(VA16)
1V9AT: C34.1 C35.1 C36.1 C37.1 C38.1 C39.1 C40.1 J23.2 J34.2 J35.2 U1.G1(VA-T1) U1.G3(VA-T2) U1.G4(VA-T3) U1.H2(VA-T4) U1.J3(VA-T5) U1.K3(VA-T6) U1.L3(VA-T7) U1.M3(VA-T8) U1.N2(VA-T9) U1.P1(VA-T10) U1.P3(VA-T11) U1.P4(VA-T12)
1V9DR: C18.1 C19.1 C20.1 C21.1 C22.1 C23.1 C24.1 C25.1 C26.1 C27.1 C28.1 C29.1 C30.1 J23.10 J42.2 J43.2 U1.A11(VDR1) U1.A15(VDR2) U1.C18(VDR3) U1.D11(VDR4) U1.D15(VDR5) U1.D17(VDR6) U1.J17(VDR7) U1.J20(VDR8) U1.R17(VDR9) U1.R20(VDR10) U1.T17(VDR11) U1.U11(VDR12) U1.U15(VDR13) U1.U16(VDR14) U1.Y11(VDR15) U1.Y15(VDR16)
1V9ENC: C46.1 C47.1 C48.1 C49.1 J23.8 J40.2 J41.2 U1.A8(VENC1) U1.B9(VENC2) U1.C8(VENC3) U1.V8(VENC4) U1.W9(VENC5) U1.Y8(VENC6)
2V2IO: C196.1 C198.1 L2.2 U17.3(IN)
2V2IO_PRE: C194.1(POS) C195.1 L2.1 L10.2 R105.1 R106.1 U16.12(OUT)
2V5IO: C169.1(POS) C170.1 C180.1 C181.1 L6.2 R91.1 U15.4(Input) U15.8(nS/D) ; also on sheet 10 11
3V3IO: C167.1 C168.1(POS) L5.1 R88.1 ; also on sheet 10 11
3V3USB: C54.1 C55.1 C56.1 C57.1 C58.1 C59.1 C60.1 C61.1 C62.1 C63.1 C67.1 C68.1 C216.1 C217.1(POS) L1.2 L11.2 R15.2 R18.1 R19.2 R20.1 R21.2 R142.2 U2.2(VCC1) U2.26(VCC2) U2.43(VCC3) U2.48(VCC4) U2.64(VCC5) U2.68(VCC6) U2.81(VCC7) U2.100(VCC8) U2.101(WAKEUP) U2.107(VCC9) U3.5(VCC) U4.8(VCC)
3V3USI1: C224.1 C225.1(POS) C245.1 J13.3 L12.2 U24.8(VCC) ; also on sheet 9 10
3V15PLL: C231.1 C232.1(POS) L13.2 ; also on sheet 8
5V0USI1: C203.1 C210.1 C211.1(POS) C221.1 C222.1 J13.1 L3.2 U17.2(EN) U17.7(BIAS) U20.4(Input) ; also on sheet 8
GND: C1.2 C2.2 C3.2 C4.2 C5.2 C6.2 C7.2 C18.2 C19.2 C20.2 C21.2 C22.2 C23.2 C24.2 C25.2 C26.2 C27.2 C28.2 C29.2 C30.2 C34.2 C35.2 C36.2 C37.2 C38.2 C39.2 C40.2 C46.2 C47.2 C48.2 C49.2 C52.2 C54.2 C55.2 C56.2 C57.2 C58.2 C59.2 C60.2 C61.2 C62.2 C63.2 C64.2(NEG) C65.2 C66.2 C67.2 C68.2 C69.1 C70.2 C71.2 C72.2 C79.2 C157.2(NEG) C158.2 C159.2 C160.2 C161.2 C167.2 C168.2(NEG) C169.2(NEG) C170.2 C175.2 C176.2 C177.2 C180.2 C181.2 C182.2(NEG) C183.2 C184.2 C186.2 C187.2 C188.1 C190.2 C192.2 C193.2 C194.2(NEG) C195.2 C196.2 C197.2 C198.2 C200.2(NEG) C201.2 C203.2 C204.2 C205.2 C206.2 C207.2 C208.2 C209.2(NEG) C210.2 C211.2(NEG) C213.2 C214.2 C215.2(NEG) C216.2 C217.2(NEG) C218.2 C220.2 C221.2 C222.2 C223.2(NEG) C224.2 C225.2(NEG) C227.2 C228.2 C229.2 C230.2(NEG) C231.2 C232.2(NEG) C234.2 C235.2 C236.2 C237.2 C239.2(NEG) C242.2(NEG) C243.2(NEG) C244.2 C245.2 D1.1(ANODE) D2.1(ANODE) D3.1(ANODE) D5.1(ANODE) D6.1(ANODE) J1.4 J2.4(GND) J3.1 J3.4 J4.3 J4.6 J4.9 J4.12 J4.15 J4.18 J4.21 J4.24 J4.27 J4.30 J16.39(GND1) J16.40(GND4) J16.41(GND2) J16.42(GND5) J16.43(GND3) J19.1 J19.2 J24.39(GND1) J24.40(GND4) J24.41(GND2) J24.42(GND5) J24.43(GND3) J25.5 J25.6 J33.5 J33.6 L9.3 LD10.2(CATHODE) R20.3 R23.2 R24.1 R89.1 R90.1 R92.1 R95.1 R97.1 R101.2 R107.1 R108.1 R109.1 R111.1 R117.1 R124.1 R130.2 R132.2 SW1.2 TP6.1 TP7.1 TP8.1 TP9.1 TP10.1 TP11.1 U1.A1(GND1) U1.A7(GND2) U1.A9(GND-E1) U1.A13(DRGND1) U1.A17(DRGND2) U1.A20(DRGND3) U1.B2(GND3) U1.B7(GND4) U1.B8(GND-E2) U1.C9(GND-E3) U1.D1(GND5) U1.D4(GND6) U1.D5(GND7) U1.D13(DRGND4) U1.D16(DRGND5) U1.E4(GND8) U1.E17(DRGND6) U1.F2(GND-T1) U1.F17(DRGND7) U1.F20(DRGND8) U1.G2(GND-T2) U1.H3(GND-T3) U1.H8(GND9) U1.H9(GND10) U1.H10(GND11) U1.H11(GND12) U1.H12(GND13) U1.H13(GND14) U1.J2(GND-T4) U1.J8(GND15) U1.J9(GND16) U1.J10(GND17) U1.J11(GND18) U1.J12(GND19) U1.J13(GND20) U1.K1(GND21) U1.K4(GND-T5) U1.K8(GND22) U1.K9(GND23) U1.K10(GND24) U1.K11(GND25) U1.K12(GND26) U1.K13(GND27) U1.L1(GND28) U1.L4(GND-T6) U1.L8(GND29) U1.L9(GND30) U1.L10(GND31) U1.L11(GND32) U1.L12(GND33) U1.L13(GND34) U1.M2(GND-T7) U1.M8(GND35) U1.M9(GND36) U1.M10(GND37) U1.M11(GND38) U1.M12(GND39) U1.M13(GND40) U1.M17(DRGND9) U1.M20(DRGND10) U1.N3(GND-T8) U1.N8(GND41) U1.N9(GND42) U1.N10(GND43) U1.N11(GND44) U1.N12(GND45) U1.N13(GND46) U1.P2(GND-T9) U1.R2(GND-T10) U1.T2(GND-C1) U1.T3(GND-C2) U1.T4(GND47) U1.U1(GND-C3) U1.U4(GND48) U1.U5(GND49) U1.U13(DRGND11) U1.U17(DRGND12) U1.V9(GND-E4) U1.V18(DRGND13) U1.W2(GND50) U1.W7(GND51) U1.W8(GND-E5) U1.Y1(GND52) U1.Y7(GND53) U1.Y9(GND-E6) U1.Y13(DRGND14) U1.Y17(DRGND15) U1.Y20(DRGND16) U2.3(GND1) U2.13(AGND1) U2.20(AGND2) U2.27(GND2) U2.33(RSVD_GND) U2.49(GND3) U2.58(GND4) U2.65(GND5) U2.80(GND6) U2.93(GND7) U2.116(GND8) U2.125(GND9) U3.1(GND1) U3.2(GND2) U4.2(A1) U4.3(A2) U4.4(GND) U4.7(WP) U13.5(GND) U13.17(PAD) U15.3(GND) U15.9(PAD) U16.10(AGND) U16.13(PGND1) U16.14(PGND2) U16.21(PAD) U17.4(GND) U17.8(PAD) U18.3(GND) U18.9(PAD) U19.3(GND) U19.9(PAD) U20.3(GND) U20.9(PAD) U21.2(GND) U22.3(GND) U22.9(PAD) U23.9(GND1) U23.10(GND2) U23.11(GND3) U23.12(AGND) U23.21(PAD) U24.5(VEE) ; also on sheet 8 9 10 11 12
VIN: C158.1 C159.1 C160.1 C187.1 C192.1 C193.1 C207.1 C208.1 C228.1 C229.1 L4.2 R82.2 R116.2 U13.11(PVIN1) U13.12(PVIN2) U13.13(PVIN3) U13.14(PVIN4) U16.3(VIN1) U16.4(VIN2) U18.4(Input) U22.4(Input) U23.5(VIN1) U23.6(VIN2) U23.15(VIN3) U23.16(VIN4)
VINI+: U1.H1(VINI+) ; also on sheet 12
VINI-: U1.J1(VINI-) ; also on sheet 12
VINQ+: U1.N1(VINQ+) ; also on sheet 12
VINQ-: U1.M1(VINQ-) ; also on sheet 12
ADC_TDIODE+: U1.E2(TDIODE+) ; also on sheet 10
ADC_TDIODE-: U1.F3(TDIODE-) ; also on sheet 10
B1/DCLK_RST+: R131.2 R132.1 R133.2 TP4.1 U1.V2(DCLK_RST+)
B1/DCLK_RST-: R129.2 R130.1 R133.1 TP3.1 U1.W1(DCLK_RST-)
B1/RCLK+: J5.5 U1.Y4(RCLK+)
B1/RCLK-: J5.6 U1.W5(RCLK-)
B1/RCOUT1+: J5.3 U1.Y5(RCOUT1+)
B1/RCOUT1-: J5.4 U1.U6(RCOUT1-)
B1/RCOUT2+: J5.1 U1.V6(RCOUT2+)
B1/RCOUT2-: J5.2 U1.V7(RCOUT2-)
B2/RXD0: J25.4 U2.51(RXD0)
B2/RXD1: J25.3 U2.53(RXD1)
B2/SDA: J20.1 R22.1 U2.37(SDA) U4.5(SDA)
B2/TXD0: J25.2 U2.50(TXD0)
B2/TXD1: J25.1 U2.52(TXD1)
B4/ENABLE1: J14.2 R96.2 R120.1 U23.19(EN)
B4/ENABLE2: J14.4 R121.1 U16.2(SD)
B4/ENABLE3: J14.6 R122.1 U18.8(nS/D) U20.8(nS/D) U22.8(nS/D)
B4/ENABLE26400: C177.1 R96.1 U13.3(EN1) U13.6(EN2)
CAL: J4.29 R128.1 ; also on sheet 9
CALDLY: J4.20 R5.1 ; also on sheet 9
CALFAIL: U1.W3(CALFAIL) ; also on sheet 9
CALRUN: U1.B5(CALRUN) ; also on sheet 9
CLKIN_N: U1.V1(CLK-) ; also on sheet 8
CLKIN_P: U1.U2(CLK+) ; also on sheet 8
CONF_CCLK: R17.2 ; also on sheet 10
CONF_DIN: U2.78(PC6/GPIFADR6) ; also on sheet 10
CONF_DONE: U2.115(PE7/GPIFADR8) ; also on sheet 10
CONF_INITB: U2.79(PC7/GPIFADR7) ; also on sheet 10
CS_N: U2.42(CS_N) ; also on sheet 9
CY_ADDR0: U2.94(A0) ; also on sheet 9
CY_ADDR1: U2.95(A1) ; also on sheet 9
CY_ADDR2: U2.96(A2) ; also on sheet 9
CY_ADDR3: U2.97(A3) ; also on sheet 9
CY_ADDR4: U2.117(A4) ; also on sheet 9
CY_ADDR5: U2.118(A5) ; also on sheet 9
CY_ADDR6: U2.119(A6) ; also on sheet 9
CY_ADDR7: U2.120(A7) ; also on sheet 9
CY_ADDR8: U2.126(A8) ; also on sheet 9
CY_ADDR9: U2.127(A9) ; also on sheet 9
CY_ADDR10: U2.128(A10) ; also on sheet 9
CY_ADDR11: U2.21(A11) ; also on sheet 9
CY_ADDR12: U2.22(A12) ; also on sheet 9
CY_ADDR13: U2.23(A13) ; also on sheet 9
CY_ADDR14: U2.24(A14) ; also on sheet 9
CY_ADDR15: U2.25(A15) ; also on sheet 9
CY_CTL3: U2.66(CTL3) ; also on sheet 10
CY_CTL4: U2.67(CTL4) ; also on sheet 10
CY_CTL5: U2.98(CTL5) ; also on sheet 10
CY_DATA0: U2.59(D0) ; also on sheet 9
CY_DATA1: U2.60(D1) ; also on sheet 9
CY_DATA2: U2.61(D2) ; also on sheet 9
CY_DATA3: U2.62(D3) ; also on sheet 9
CY_DATA4: U2.63(D4) ; also on sheet 9
CY_DATA5: U2.86(D5) ; also on sheet 9
CY_DATA6: U2.87(D6) ; also on sheet 9
CY_DATA7: U2.88(D7) ; also on sheet 9
CY_FD0: U2.44(PB0/FD0) ; also on sheet 9
CY_FD1: U2.45(PB1/FD1) ; also on sheet 9
CY_FD2: U2.46(PB2/FD2) ; also on sheet 9
CY_FD3: U2.47(PB3/FD3) ; also on sheet 9
CY_FD4: U2.54(PB4/FD4) ; also on sheet 9
CY_FD5: U2.55(PB5/FD5) ; also on sheet 9
CY_FD6: U2.56(PB6/FD6) ; also on sheet 9
CY_FD7: U2.57(PB7/FD7) ; also on sheet 9
CY_FD8: U2.102(PD0/FD8) ; also on sheet 9
CY_FD9: U2.103(PD1/FD9) ; also on sheet 9
CY_FD10: U2.104(PD2/FD10) ; also on sheet 9
CY_FD11: U2.105(PD3/FD11) ; also on sheet 9
CY_FD12: U2.121(PD4/FD12) ; also on sheet 9
CY_FD13: U2.122(PD5/FD13) ; also on sheet 9
CY_FD14: U2.123(PD6/FD14) ; also on sheet 9
CY_FD15: U2.124(PD7/FD15) ; also on sheet 9
CY_ID0: U2.72(PC0/GPIFADR0) ; also on sheet 9
CY_ID1: U2.73(PC1/GPIFADR1) ; also on sheet 9
CY_ID2: U2.74(PC2/GPIFADR2) ; also on sheet 9
CY_ID3: U2.75(PC3/GPIFADR3) ; also on sheet 9
CY_REQ: R13.2 ; also on sheet 9
CY_VALID: U2.114(PE6/T2EX) ; also on sheet 9
DCLKI+: U1.K19(DCLKI+) ; also on sheet 9
DCLKI-: U1.K20(DCLKI-) ; also on sheet 9
DCLKQ+: U1.L19(DCLKQ+) ; also on sheet 9
DCLKQ-: U1.L20(DCLKQ-) ; also on sheet 9
DDRPHASE: J4.17 R3.1 ; also on sheet 9
DES: J4.11 R6.1 ; also on sheet 9
DI+0: U1.B18(DI0+) ; also on sheet 9
DI+1: U1.B19(DI1+) ; also on sheet 9
DI+2: U1.C19(DI2+) ; also on sheet 9
DI+3: U1.D18(DI3+) ; also on sheet 9
DI+4: U1.D19(DI4+) ; also on sheet 9
DI+5: U1.E19(DI5+) ; also on sheet 9
DI+6: U1.F18(DI6+) ; also on sheet 9
DI+7: U1.G17(DI7+) ; also on sheet 9
DI+8: U1.G19(DI8+) ; also on sheet 9
DI+9: U1.H17(DI9+) ; also on sheet 9
DI+10: U1.H19(DI10+) ; also on sheet 9
DI+11: U1.J18(DI11+) ; also on sheet 9
DI-0: U1.C17(DI0-) ; also on sheet 9
DI-1: U1.B20(DI1-) ; also on sheet 9
DI-2: U1.C20(DI2-) ; also on sheet 9
DI-3: U1.E18(DI3-) ; also on sheet 9
DI-4: U1.D20(DI4-) ; also on sheet 9
DI-5: U1.E20(DI5-) ; also on sheet 9
DI-6: U1.F19(DI6-) ; also on sheet 9
DI-7: U1.G18(DI7-) ; also on sheet 9
DI-8: U1.G20(DI8-) ; also on sheet 9
DI-9: U1.H18(DI9-) ; also on sheet 9
DI-10: U1.H20(DI10-) ; also on sheet 9
DI-11: U1.J19(DI11-) ; also on sheet 9
DID+0: U1.A10(DID0+) ; also on sheet 9
DID+1: U1.C10(DID1+) ; also on sheet 9
DID+2: U1.B11(DID2+) ; also on sheet 9
DID+3: U1.A12(DID3+) ; also on sheet 9
DID+4: U1.C12(DID4+) ; also on sheet 9
DID+5: U1.B13(DID5+) ; also on sheet 9
DID+6: U1.A14(DID6+) ; also on sheet 9
DID+7: U1.C14(DID7+) ; also on sheet 9
DID+8: U1.B15(DID8+) ; also on sheet 9
DID+9: U1.A16(DID9+) ; also on sheet 9
DID+10: U1.B17(DID10+) ; also on sheet 9
DID+11: U1.A18(DID11+) ; also on sheet 9
DID-0: U1.B10(DID0-) ; also on sheet 9
DID-1: U1.D10(DID1-) ; also on sheet 9
DID-2: U1.C11(DID2-) ; also on sheet 9
DID-3: U1.B12(DID3-) ; also on sheet 9
DID-4: U1.D12(DID4-) ; also on sheet 9
DID-5: U1.C13(DID5-) ; also on sheet 9
DID-6: U1.B14(DID6-) ; also on sheet 9
DID-7: U1.D14(DID7-) ; also on sheet 9
DID-8: U1.C15(DID8-) ; also on sheet 9
DID-9: U1.B16(DID9-) ; also on sheet 9
DID-10: U1.C16(DID10-) ; also on sheet 9
DID-11: U1.A19(DID11-) ; also on sheet 9
DQ+0: U1.W18(DQ0+) ; also on sheet 9
DQ+1: U1.W19(DQ1+) ; also on sheet 9
DQ+2: U1.V19(DQ2+) ; also on sheet 9
DQ+3: U1.U18(DQ3+) ; also on sheet 9
DQ+4: U1.U19(DQ4+) ; also on sheet 9
DQ+5: U1.T19(DQ5+) ; also on sheet 9
DQ+6: U1.R18(DQ6+) ; also on sheet 9
DQ+7: U1.P17(DQ7+) ; also on sheet 9
DQ+8: U1.P19(DQ8+) ; also on sheet 9
DQ+9: U1.N17(DQ9+) ; also on sheet 9
DQ+10: U1.N19(DQ10+) ; also on sheet 9
DQ+11: U1.M18(DQ11+) ; also on sheet 9
DQ-0: U1.V17(DQ0-) ; also on sheet 9
DQ-1: U1.W20(DQ1-) ; also on sheet 9
DQ-2: U1.V20(DQ2-) ; also on sheet 9
DQ-3: U1.T18(DQ3-) ; also on sheet 9
DQ-4: U1.U20(DQ4-) ; also on sheet 9
DQ-5: U1.T20(DQ5-) ; also on sheet 9
DQ-6: U1.R19(DQ6-) ; also on sheet 9
DQ-7: U1.P18(DQ7-) ; also on sheet 9
DQ-8: U1.P20(DQ8-) ; also on sheet 9
DQ-9: U1.N18(DQ9-) ; also on sheet 9
DQ-10: U1.N20(DQ10-) ; also on sheet 9
DQ-11: U1.M19(DQ11-) ; also on sheet 9
DQD+0: U1.Y10(DQD0+) ; also on sheet 9
DQD+1: U1.V10(DQD1+) ; also on sheet 9
DQD+2: U1.W11(DQD2+) ; also on sheet 9
DQD+3: U1.Y12(DQD3+) ; also on sheet 9
DQD+4: U1.V12(DQD4+) ; also on sheet 9
DQD+5: U1.W13(DQD5+) ; also on sheet 9
DQD+6: U1.Y14(DQD6+) ; also on sheet 9
DQD+7: U1.V14(DQD7+) ; also on sheet 9
DQD+8: U1.W15(DQD8+) ; also on sheet 9
DQD+9: U1.Y16(DQD9+) ; also on sheet 9
DQD+10: U1.W17(DQD10+) ; also on sheet 9
DQD+11: U1.Y18(DQD11+) ; also on sheet 9
DQD-0: U1.W10(DQD0-) ; also on sheet 9
DQD-1: U1.U10(DQD1-) ; also on sheet 9
DQD-2: U1.V11(DQD2-) ; also on sheet 9
DQD-3: U1.W12(DQD3-) ; also on sheet 9
DQD-4: U1.U12(DQD4-) ; also on sheet 9
DQD-5: U1.V13(DQD5-) ; also on sheet 9
DQD-6: U1.W14(DQD6-) ; also on sheet 9
DQD-7: U1.U14(DQD7-) ; also on sheet 9
DQD-8: U1.V15(DQD8-) ; also on sheet 9
DQD-9: U1.W16(DQD9-) ; also on sheet 9
DQD-10: U1.V16(DQD10-) ; also on sheet 9
DQD-11: U1.Y19(DQD11-) ; also on sheet 9
ECE: J4.8 R4.1 ; also on sheet 9
EXP_A_N0: J16.1(GP2e) ; also on sheet 10
EXP_A_N1: J16.3(GP1e) ; also on sheet 10
EXP_A_N2: J16.5(CLKe) ; also on sheet 10
EXP_A_N3: J16.7(D15e) ; also on sheet 10
EXP_A_N4: J16.9(D14e) ; also on sheet 10
EXP_A_N5: J16.11(D13e) ; also on sheet 10
EXP_A_N6: J16.13(D12e) ; also on sheet 10
EXP_A_N7: J16.15(D11e) ; also on sheet 10
EXP_A_N8: J16.17(D10e) ; also on sheet 10
EXP_A_N9: J16.19(D9e) ; also on sheet 10
EXP_A_N10: J16.21(D8e) ; also on sheet 10
EXP_A_N11: J16.23(D7e) ; also on sheet 10
EXP_A_N12: J16.25(D6e) ; also on sheet 10
EXP_A_N13: J16.27(D5e) ; also on sheet 10
EXP_A_N14: J16.29(D4e) ; also on sheet 10
EXP_A_N15: J16.31(D3e) ; also on sheet 10
EXP_A_N16: J16.33(D2e) ; also on sheet 10
EXP_A_N17: J16.35(D1e) ; also on sheet 10
EXP_A_N18: J16.37(D0e) ; also on sheet 10
EXP_A_P0: J16.2(GP2o) ; also on sheet 10
EXP_A_P1: J16.4(GP1o) ; also on sheet 10
EXP_A_P2: J16.6(CLKo) ; also on sheet 10
EXP_A_P3: J16.8(D15o) ; also on sheet 10
EXP_A_P4: J16.10(D14o) ; also on sheet 10
EXP_A_P5: J16.12(D13o) ; also on sheet 10
EXP_A_P6: J16.14(D12o) ; also on sheet 10
EXP_A_P7: J16.16(D11o) ; also on sheet 10
EXP_A_P8: J16.18(D10o) ; also on sheet 10
EXP_A_P9: J16.20(D9o) ; also on sheet 10
EXP_A_P10: J16.22(D8o) ; also on sheet 10
EXP_A_P11: J16.24(D7o) ; also on sheet 10
EXP_A_P12: J16.26(D6o) ; also on sheet 10
EXP_A_P13: J16.28(D5o) ; also on sheet 10
EXP_A_P14: J16.30(D4o) ; also on sheet 10
EXP_A_P15: J16.32(D3o) ; also on sheet 10
EXP_A_P16: J16.34(D2o) ; also on sheet 10
EXP_A_P17: J16.36(D1o) ; also on sheet 10
EXP_A_P18: J16.38(D0o) ; also on sheet 10
EXP_B_N0: J24.1(GP2e) ; also on sheet 9
EXP_B_N1: J24.3(GP1e) ; also on sheet 9
EXP_B_N2: J24.5(CLKe) ; also on sheet 9
EXP_B_N3: J24.7(D15e) ; also on sheet 9
EXP_B_N4: J24.9(D14e) ; also on sheet 9
EXP_B_N5: J24.11(D13e) ; also on sheet 9
EXP_B_N6: J24.13(D12e) ; also on sheet 9
EXP_B_N7: J24.15(D11e) ; also on sheet 9
EXP_B_N8: J24.17(D10e) ; also on sheet 9
EXP_B_N9: J24.19(D9e) ; also on sheet 9
EXP_B_N10: J24.21(D8e) ; also on sheet 9
EXP_B_N11: J24.23(D7e) ; also on sheet 9
EXP_B_N12: J24.25(D6e) ; also on sheet 9
EXP_B_N13: J24.27(D5e) ; also on sheet 9
EXP_B_N14: J24.29(D4e) ; also on sheet 9
EXP_B_N15: J24.31(D3e) ; also on sheet 9
EXP_B_N16: J24.33(D2e) ; also on sheet 9
EXP_B_N17: J24.35(D1e) ; also on sheet 9
EXP_B_N18: J24.37(D0e) ; also on sheet 9
EXP_B_P0: J24.2(GP2o) ; also on sheet 9
EXP_B_P1: J24.4(GP1o) ; also on sheet 9
EXP_B_P2: J24.6(CLKo) ; also on sheet 9
EXP_B_P3: J24.8(D15o) ; also on sheet 9
EXP_B_P4: J24.10(D14o) ; also on sheet 9
EXP_B_P5: J24.12(D13o) ; also on sheet 9
EXP_B_P6: J24.14(D12o) ; also on sheet 9
EXP_B_P7: J24.16(D11o) ; also on sheet 9
EXP_B_P8: J24.18(D10o) ; also on sheet 9
EXP_B_P9: J24.20(D9o) ; also on sheet 9
EXP_B_P10: J24.22(D8o) ; also on sheet 9
EXP_B_P11: J24.24(D7o) ; also on sheet 9
EXP_B_P12: J24.26(D6o) ; also on sheet 9
EXP_B_P13: J24.28(D5o) ; also on sheet 9
EXP_B_P14: J24.30(D4o) ; also on sheet 9
EXP_B_P15: J24.32(D3o) ; also on sheet 9
EXP_B_P16: J24.34(D2o) ; also on sheet 9
EXP_B_P17: J24.36(D1o) ; also on sheet 9
EXP_B_P18: J24.38(D0o) ; also on sheet 9
FIFOADR0: U2.89(PA4/FIFOADR0) ; also on sheet 9
FIFOADR1: U2.90(PA5/FIFOADR1) ; also on sheet 9
FLAGA: U2.69(CTL0/FLAGA) ; also on sheet 9
FLAGB: U2.70(CTL1/FLAGB) ; also on sheet 9
FLAGC: U2.71(CTL2/FLAGC) ; also on sheet 9
FPGA_RESET: R15.1 R16.2 ; also on sheet 9
FSR: J4.14 R2.1 ; also on sheet 9
IFCLK: U2.32(IFCLK) ; also on sheet 10
LOAD_STATE: R14.2 ; also on sheet 9
NC: J16.44(NC) J24.44(NC)
NDM: J4.26 R127.1 ; also on sheet 9
ORI+: U1.K17(ORI+) ; also on sheet 9
ORI-: U1.K18(ORI-) ; also on sheet 9
ORQ+: U1.L17(ORQ+) ; also on sheet 9
ORQ-: U1.L18(ORQ-) ; also on sheet 9
PDI: J4.2 R9.1 ; also on sheet 9
PDQ: J4.5 R25.1 ; also on sheet 9
PKTEND: U2.91(PA6/PKTEND) ; also on sheet 9
PORen: J33.3 R139.1 ; also on sheet 9
PROGRAMB: U2.76(PC4/GPIFADR4) ; also on sheet 10
RD_N: U2.40(RD_N) ; also on sheet 9
SCL_FROM_CY: R19.1 U2.36(SCL) U4.6(SCL) ; also on sheet 10
SCLK: U1.C5(SCLK) ; also on sheet 9
SCS: U1.C4(SCS) ; also on sheet 9
SDA_FROM_CY: J20.2 R21.1 R22.2 ; also on sheet 10
SDI: U1.B4(SDI) ; also on sheet 9
SDO: U1.A3(SDO) ; also on sheet 9
SLCS_N: U2.92(PA7/FLGD/SLCS_N) ; also on sheet 9
SLOE: U2.84(PA2/SLOE) ; also on sheet 9
SLRD: U2.4(RDY0/SLRD) ; also on sheet 9
SLWR: U2.5(RDY1/SLWR) ; also on sheet 9
STATE0: U2.108(PE0/T0OUT) ; also on sheet 10
STATE1: U2.109(PE1/T1OUT) ; also on sheet 10
STATE2: U2.110(PE2/T2OUT) ; also on sheet 10
STATE3: U2.111(PE3/RXD0OUT) ; also on sheet 10
TPM: J4.23 R8.1 ; also on sheet 9
USB_PWR: C213.1 C214.1 J2.1(VBUS) U19.4(Input) U19.8(nS/D)
V_USI1: J13.2 ; also on sheet 10
VCMO: U1.C2(VCMO) ; also on sheet 10
VNEGI: C79.1 J3.2 U1.D7(VNEGI1) U1.J4(VNEGI2) U1.K2(VNEGI3)
VNEGQ: C72.1 J3.3 U1.L2(VNEGQ1) U1.M4(VNEGQ2) U1.U7(VNEGQ3)
WE_N: U2.41(WR_N) ; also on sheet 9
WSS: J33.4 R138.1 ; also on sheet 9
B1/N17676120: TP1.1 U1.B1(VBG)
B1/N17676520: R12.1 U1.C3(REXT+)
B1/N17676524: R12.2 U1.D3(REXT-)
B1/N17676530: R7.1 U1.C1(RTRIM+)
B1/N17676534: R7.2 U1.D2(RTRIM-)
B1/N17846912: R9.2 U1.U3(PDI)
B1/N17848835: R25.2 U1.V3(PDQ)
B1/N17849798: R2.2 U1.Y3(FSR)
B1/N17850762: R3.2 U1.W4(DDRPHASE)
B1/N17851727: R4.2 U1.B3(ECE)
B1/N17852693: R5.2 U1.V4(CALDLY)
B1/N17853660: R6.2 U1.V5(DES)
B1/N17854628: R8.2 U1.A4(TPM)
B1/N18067453: R10.2 U1.E3(VTEST+)
B1/N18068484: R11.2 U1.F4(VTEST-)
B1/N18075731: J1.2 R10.1
B1/N18078831: J1.3 R11.1
B1/N19099019: R127.2 U1.A5(NDM)
B1/N19100077: R128.2 U1.D6(CAL)
B1/N19255100: J19.3 U24.2(D+)
B1/N19265006: R131.1 U24.7(Q+)
B1/N19266083: R129.1 U24.6(Q-)
B1/N19380996: U24.3(D-) U24.4(VBB)
B1/N19554045: R139.2 U1.C6(POREN)
B1/N19574264: R138.2 U1.C7(WSS)
B2/N16721567: J2.3(D+) U2.18(DPLUS)
B2/N16721659: J2.2(D-) U2.19(DMINUS)
B2/N16722721: C69.2 J2.5(SHELL_1) J2.6(SHELL_2) R24.2
B2/N16727306: R23.1 U2.35(EA)
B2/N17041129: R18.2 U2.99(RESET_N) U3.3(RESET_N)
B2/N17122999: R20.2 U4.1(A0)
B2/N17127467: R16.1 U2.85(PA3/WU2)
B2/N17138281: C64.1(POS) C65.1 C66.1 L1.1 U2.10(AVCC1) U2.17(AVCC2)
B2/N17237535: LD11.2(CATHODE) U2.82(PA0/INT0_N)
B2/N17238039: LD11.1(ANODE) R142.1
B2/N17268771: SW1.1 U3.4(MR_N)
B2/N17383940: C70.1 U2.11(XTALOUT) Y1.1
B2/N17383990: C71.1 U2.12(XTALIN) Y1.2
B2/N17384219: TP2.1 U2.1(CLKOUT)
B2/N18092594: R13.1 U2.113(PE5/INT6)
B2/N18092628: R14.1 U2.112(PE4/RXD1OUT)
B2/N18102458: R17.1 U2.77(PC5/GPIFADR5)
B4/N16769321: C164.1 D2.2(CATHODE) L5.2 U13.15(SW1)
B4/N16769692: C175.1 U13.2(SS1)
B4/N16769839: R88.2 R89.2 U13.1(FB1)
B4/N16770680: C164.2 U13.16(BST1)
B4/N16772680: C161.1 R82.1 U13.4(AVIN)
B4/N16798185: C188.2 C190.1 U16.1(VCC)
B4/N16803121: C191.2 R103.1 U16.6(COMP)
B4/N16805297: C191.1 C202.1 R105.2 R106.2 R107.2 U16.7(FB)
B4/N16807514: C202.2 R103.2
B4/N16809137: R108.2 U16.8(RT)
B4/N16815468: C206.1 U16.9(RAMP)
B4/N16819191: C189.1 U16.20(BST)
B4/N16819385: C189.2 D4.2(CATHODE) L10.1 U16.17(SW1) U16.18(SW2)
B4/N16821177: D4.1(ANODE) U16.15(IS1) U16.16(IS2)
B4/N16824930: C205.1 U16.11(SS)
B4/N16835182: C204.1 U17.1(SS)
B4/N16860475: C218.1 U18.1(Bypass)
B4/N16862731: C212.1 R109.2 R110.2 U18.6(ADJ)
B4/N16862763: C209.1(POS) C212.2 L3.1 R110.1 U18.5(Output)
B4/N16907733: C165.1 D3.2(CATHODE) L6.1 U13.10(SW2)
B4/N16907748: C176.1 U13.7(SS2)
B4/N16907762: R90.2 R91.2 U13.8(FB2)
B4/N16907804: C165.2 U13.9(BST2)
B4/N16954081: C215.1(POS) C219.2 L11.1 R112.1 U19.5(Output)
B4/N16954093: C220.1 U19.1(Bypass)
B4/N16954109: C219.1 R111.2 R112.2 U19.6(ADJ)
B4/N16954745: C223.1(POS) C226.2 L12.1 R118.1 U20.5(Output)
B4/N16954757: C227.1 U20.1(Bypass)
B4/N16954773: C226.1 R117.2 R118.2 U20.6(ADJ)
B4/N17034359: D6.2(CATHODE) R116.1 R120.2 R121.2 R122.2 U21.1(VCC) U21.3(EN)
B4/N17039443: J14.1 U21.6(FLAG1)
B4/N17039809: J14.3 U21.5(FLAG2)
B4/N17040176: J14.5 U21.4(FLAG3)
B4/N17209995: J12.2(A) L9.2
B4/N17221364: C157.1(POS) L4.1 R99.2 SW2.2
B4/N17247885: LD10.1(ANODE) R99.1
B4/N17271500: C186.1 U15.1(Bypass)
B4/N17271514: C185.1 R97.2 R98.2 U15.6(ADJ)
B4/N17272516: C230.1(POS) C233.2 L13.1 R125.1 U22.5(Output)
B4/N17272520: C234.1 U22.1(Bypass)
B4/N17272540: C233.1 R124.2 R125.2 U22.6(ADJ)
B4/N17400918: R92.2 U23.20(RT)
B4/N17401691: R93.2 U23.4(COMP)
B4/N17402468: C235.1 U23.1(SS/TRK)
B4/N17411980: C236.1 R93.1
B4/N17421515: C237.1 U23.18(VCC)
B4/N17425568: R94.2 R95.2 U23.2(FB)
B4/N17434478: C238.2 D1.2(CATHODE) D5.2(CATHODE) L7.1 U23.7(SW1) U23.8(SW2) U23.13(SW3) U23.14(SW4)
B4/N17462336: C197.1 C239.1(POS) L7.2 L8.1 R94.1
B4/N17645952: C199.1 R101.1 R102.2 U17.5(ADJ)
B4/N17645980: C199.2 C200.1(POS) C201.1 J22.1 R102.1 U17.6(OUT)
B4/N17751700: J21.1 L9.4
B4/N17752133: J21.2 SW2.3
B4/N17824195: J12.1(C) L9.1
B4/N18005197: J22.2 L14.1
N18073898: C238.1 U23.17(BOOT)

Not connected (* = marked no-connect by the designer): J12 3(B)*; SW2 1*; U2 6(RDY2)* 7(RDY3)* 8(RDY4)* 9(RDY5)* 14(NC1)* 15(NC2)* 16(NC3)* 28(INT4)* 29(T0)* 30(T1)* 31(T2)* 34(BKPT)* 38(OE_N)* 39(PSEN_N)* 83(PA1/INT1_N) 106(INT5_N)*; U15 2(NC1)* 7(NC2)*; U16 5(SYNC)* 19(PRE)*; U18 2(NC1)* 7(NC2)*; U19 2(NC1)* 7(NC2)*; U20 2(NC1)* 7(NC2)*; U22 2(NC1)* 7(NC2)*; U23 3(PGOOD)*; U24 1(NC)*

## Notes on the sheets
sheet 1
- ADC12DX00RF Reference Board
- REFERENCE DESIGN
- SPECIAL NOTES
- These schematics reflect the current state of product development. This design
  had NOT yet been fully tested at the time these schematics were generated.
- Since this product is in development, the user of this document is
  strongly advised to check for the latest revision.
- National Semiconductor reserves the right to make changes to this product.
- ALL parts labeled "NA" are NOT ASSEMBLED.
- Print Instructions:
   - To create a readable printout, we recommend to use A3 or 11x17" paper size.
   - When printing from this PDF file, make sure to check the "Shrink to fit" box.
- CONFIDENTIAL
- THIS DOCUMENT CONTAINS INFORMATION PROPRIETARY TO
  NATIONAL SEMICONDUCTOR CORPORATION.  USE OR
  DISCLOSURE      WITHOUT     WRITTEN    PERMISSION    IS
  EXPRESSLY    FORBIDDEN.                      COPYRIGHT  2007.
- PRELIMINARY
sheet 2
- Cypress uC
- Power
- ADC12Dx00
- Virtex-4
- Expansion
- FRONT
  END
- PLL
sheet 3
- Power Supply Jumper
- DCLK_RST SINGLE ENDED INPUT
- Do not populate R133.
  Pads must be placed near ADC.
sheet 4
- Place near pin 26
- EEPROM
sheet 5
- 2V5IO - FPGA IO BANK SUPPLY, FPGA CORE
  AUXILIARY SUPPLY, EXPANSION HEADERS SUPPLY
- 3V3IO - FPGA IO BANK SUPPLY
- 1V2VCC_INT - FPGA CORE SUPPLY
- 1V8IO - ADC IO SUPPLY, FPGA IO BANK SUPPLY
- MAIN INPUT JACK
- 2V2IO/2V2_PRE - NOT USED (INTERMEDIATE SUPPLY ONLY)
- 1V9A - ADC ANALOG SUPPLY
- 5V0USI1 - USI1 HEADER SUPPLY, FPGA IO BANK SUPPLY (JUMPER SELECTABLE)
- MAIN USI1 SUPPLY SELECTION
- 3V3USB - CYPRESS uC & EEPROM USB SUPPLY
- SEQUENCING CONTROL
- 3V3USI1 - USI1 HEADER SUPPLY, FPGA IO BANK SUPPLY (JUMPER SELECTABLE)
sheet 6
- 3V0PLL - LMX2531 CLOCK GENERATOR SUPPLY
sheet 7
- LOGIC ANALYZER HEADER
- LOGIC ANALYZER HEADER
